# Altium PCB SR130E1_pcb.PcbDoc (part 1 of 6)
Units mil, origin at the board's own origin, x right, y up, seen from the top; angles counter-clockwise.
Board outline 5700 x 4800 mil, 6 copper layers (Top Layer, Signal Layer 1, Signal Layer 2, Signal Layer 3, Signal Layer 4, Bottom Layer), stack 61.4 mil thick; 452 components, 288 nets, 1391 pads, 911 vias.
Unrouted connection lines stored in the file: 523.
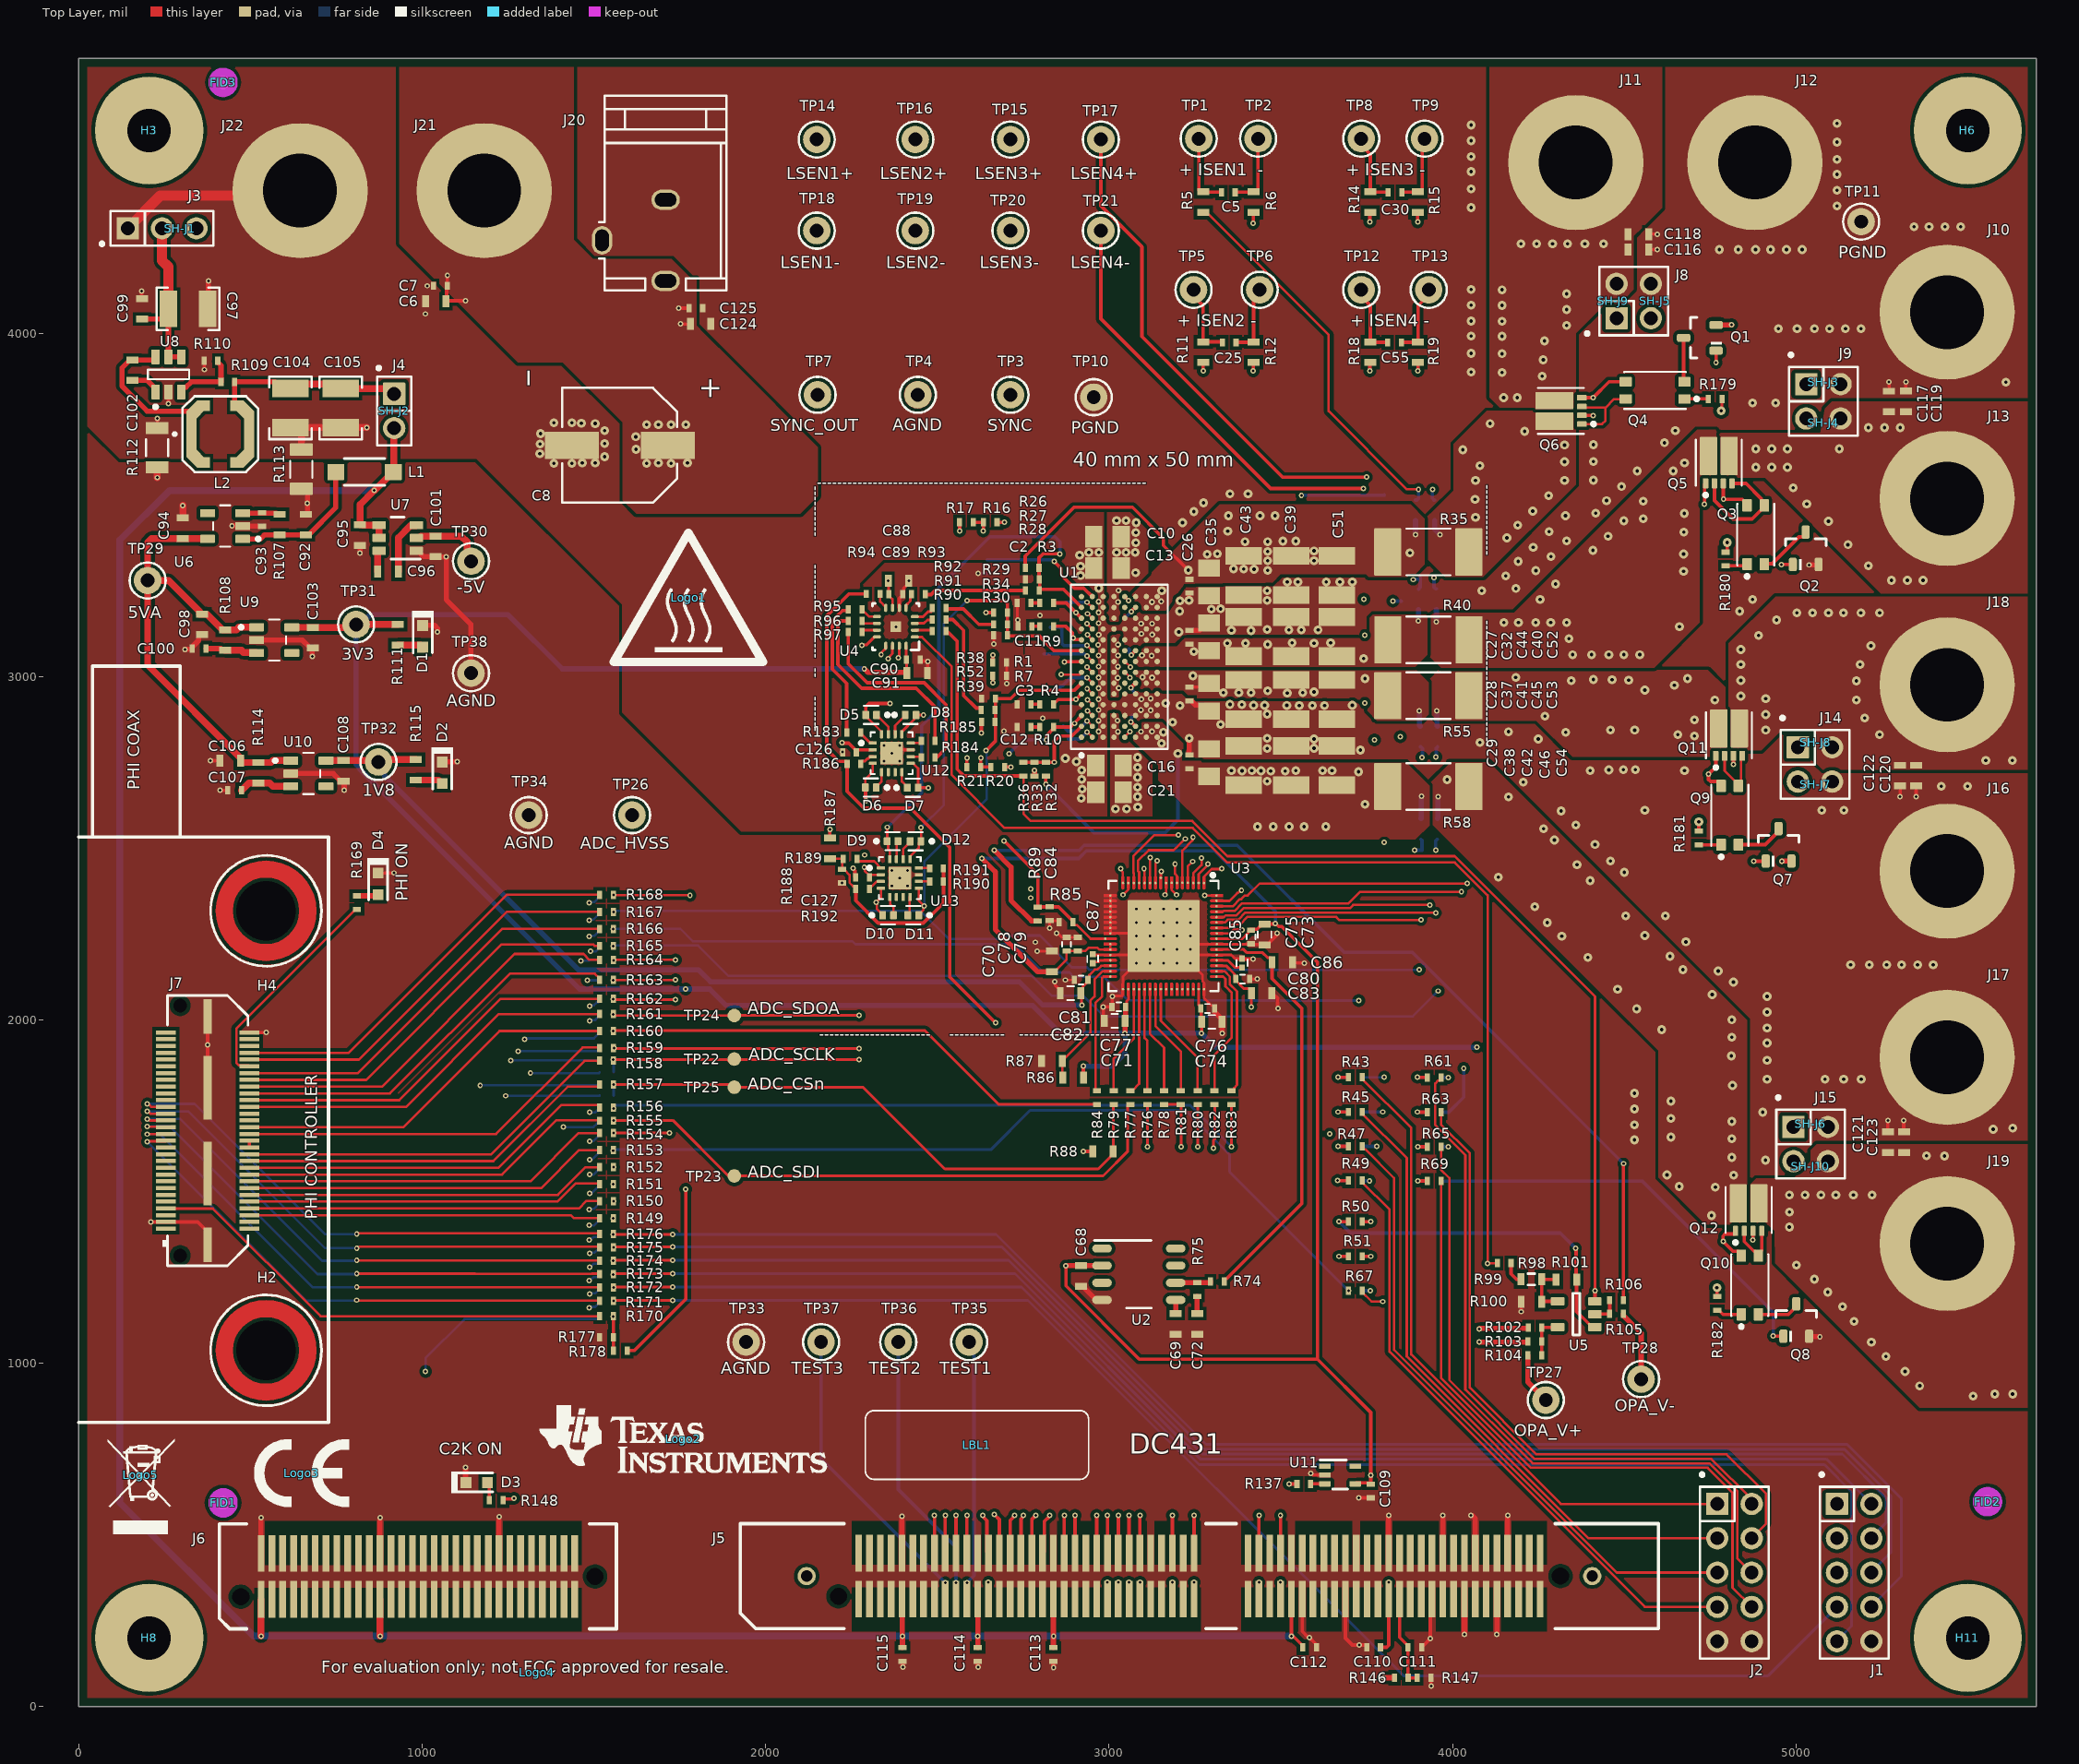
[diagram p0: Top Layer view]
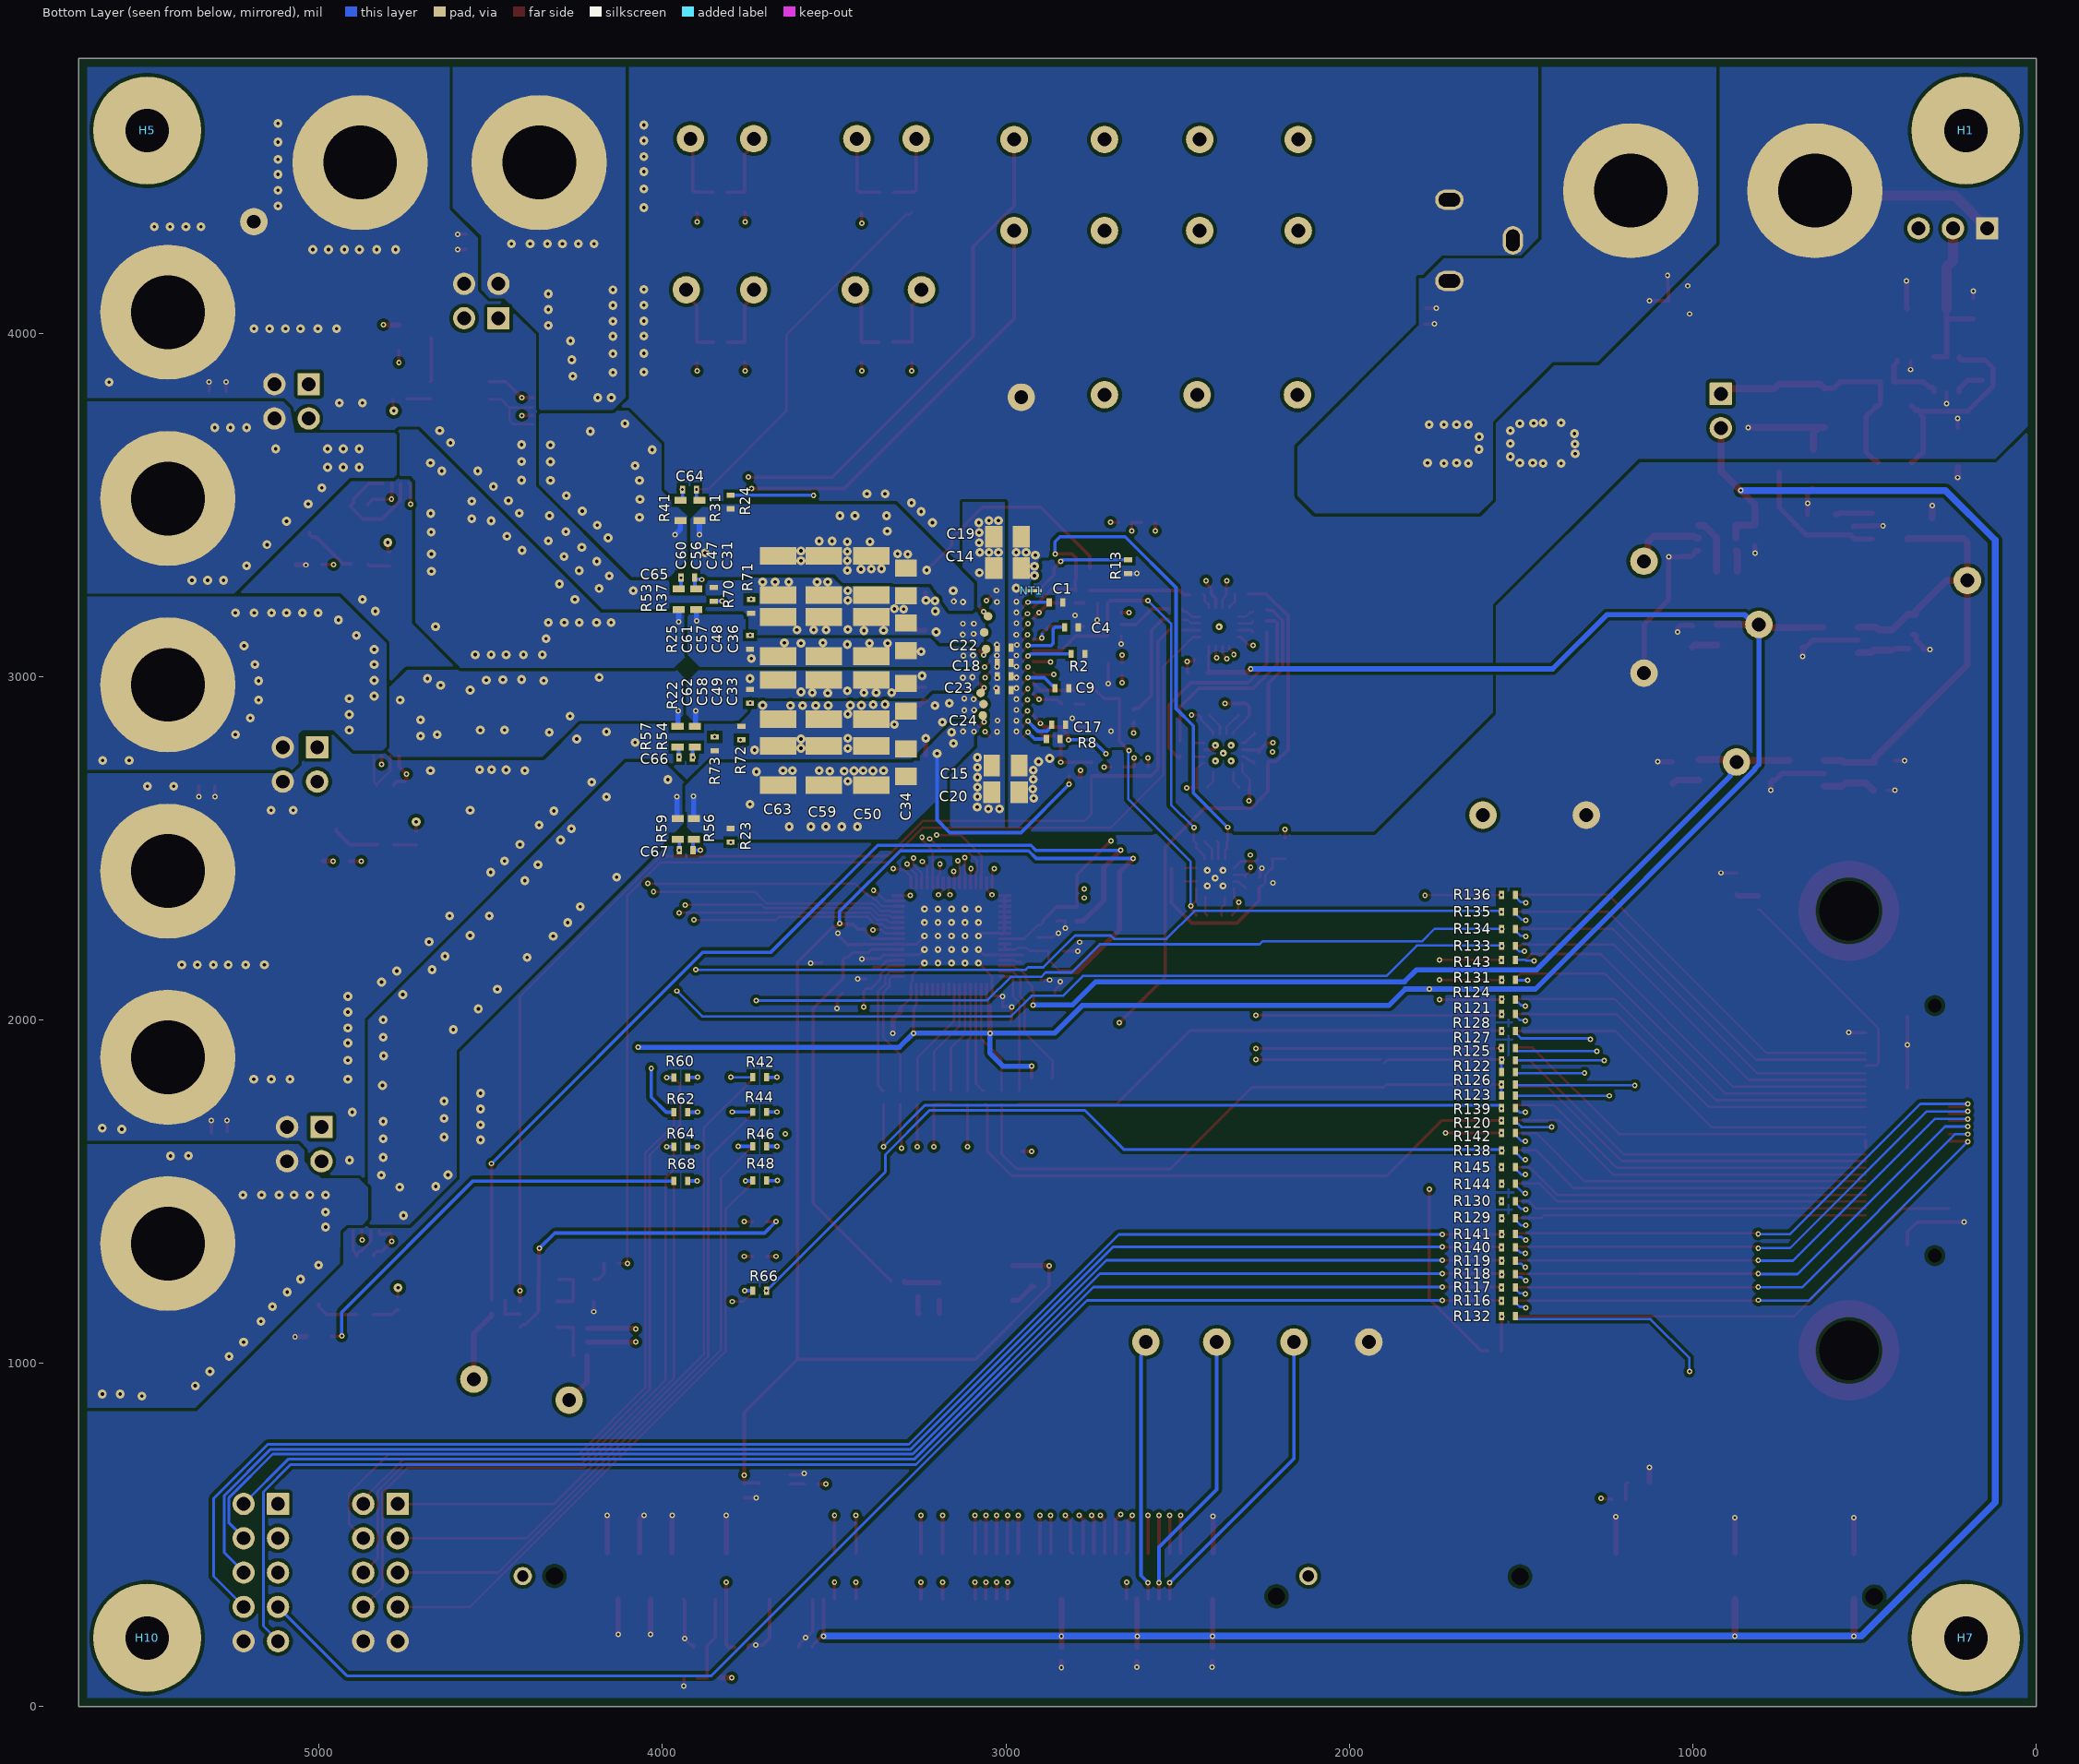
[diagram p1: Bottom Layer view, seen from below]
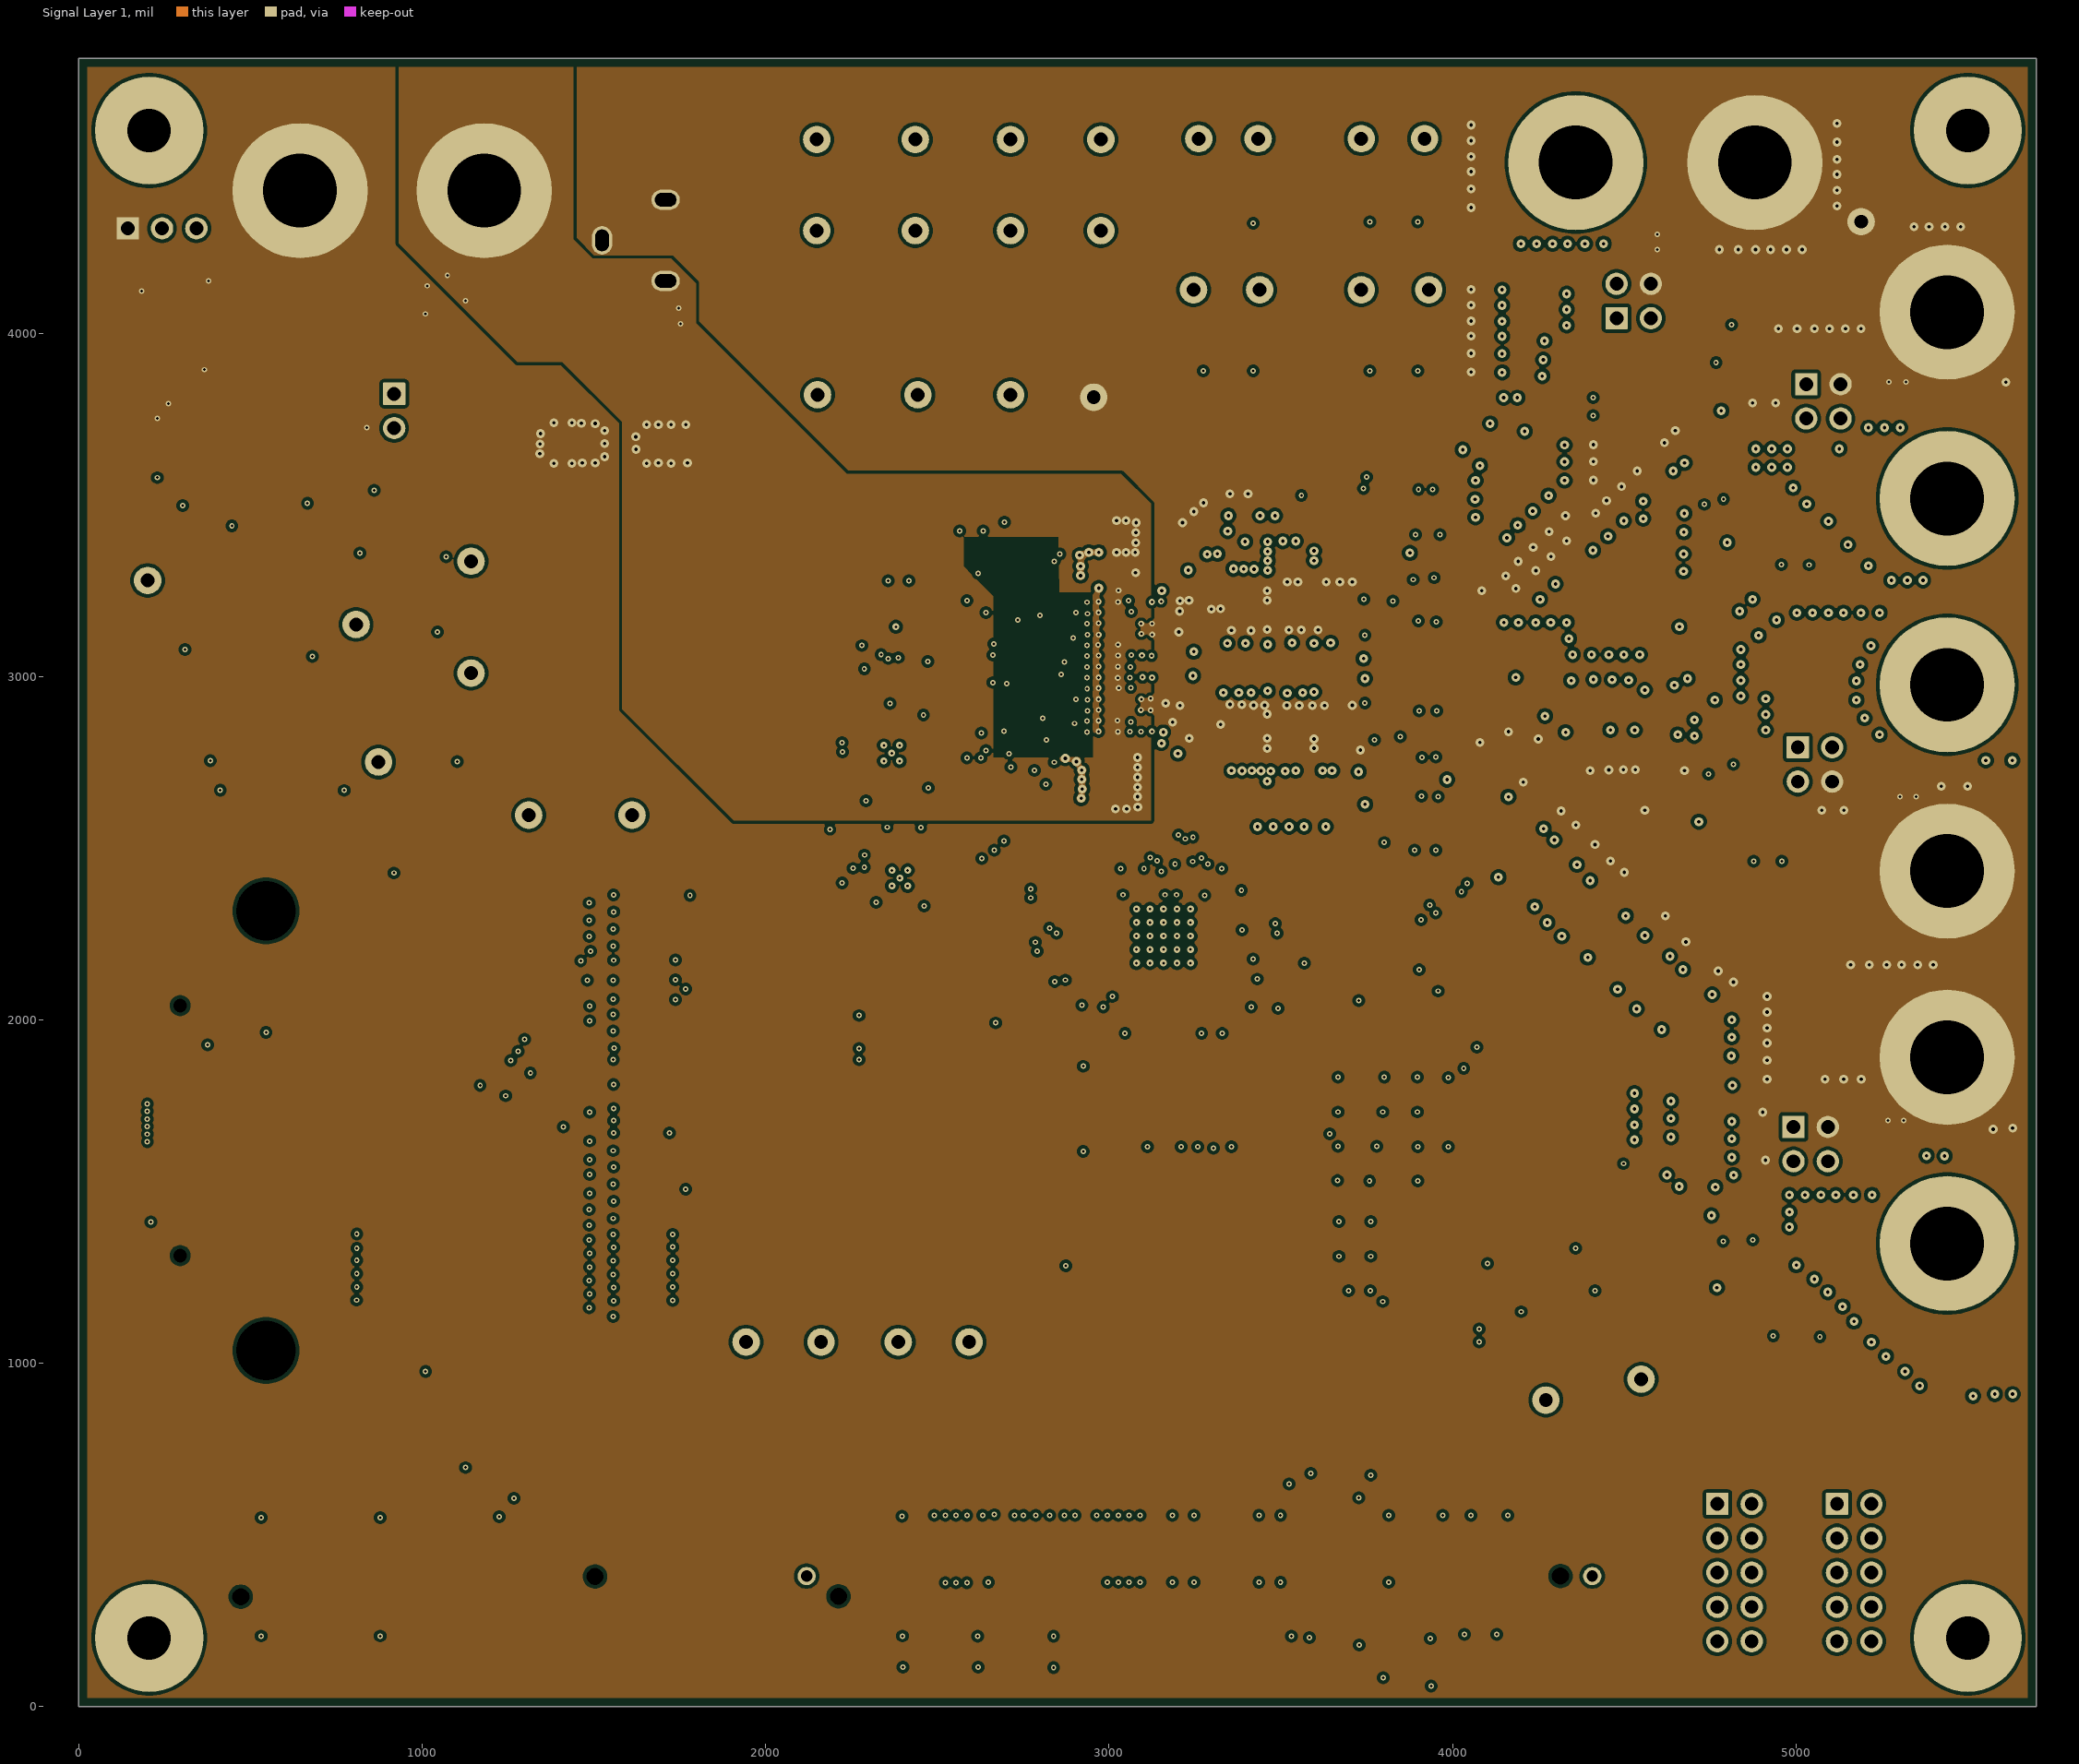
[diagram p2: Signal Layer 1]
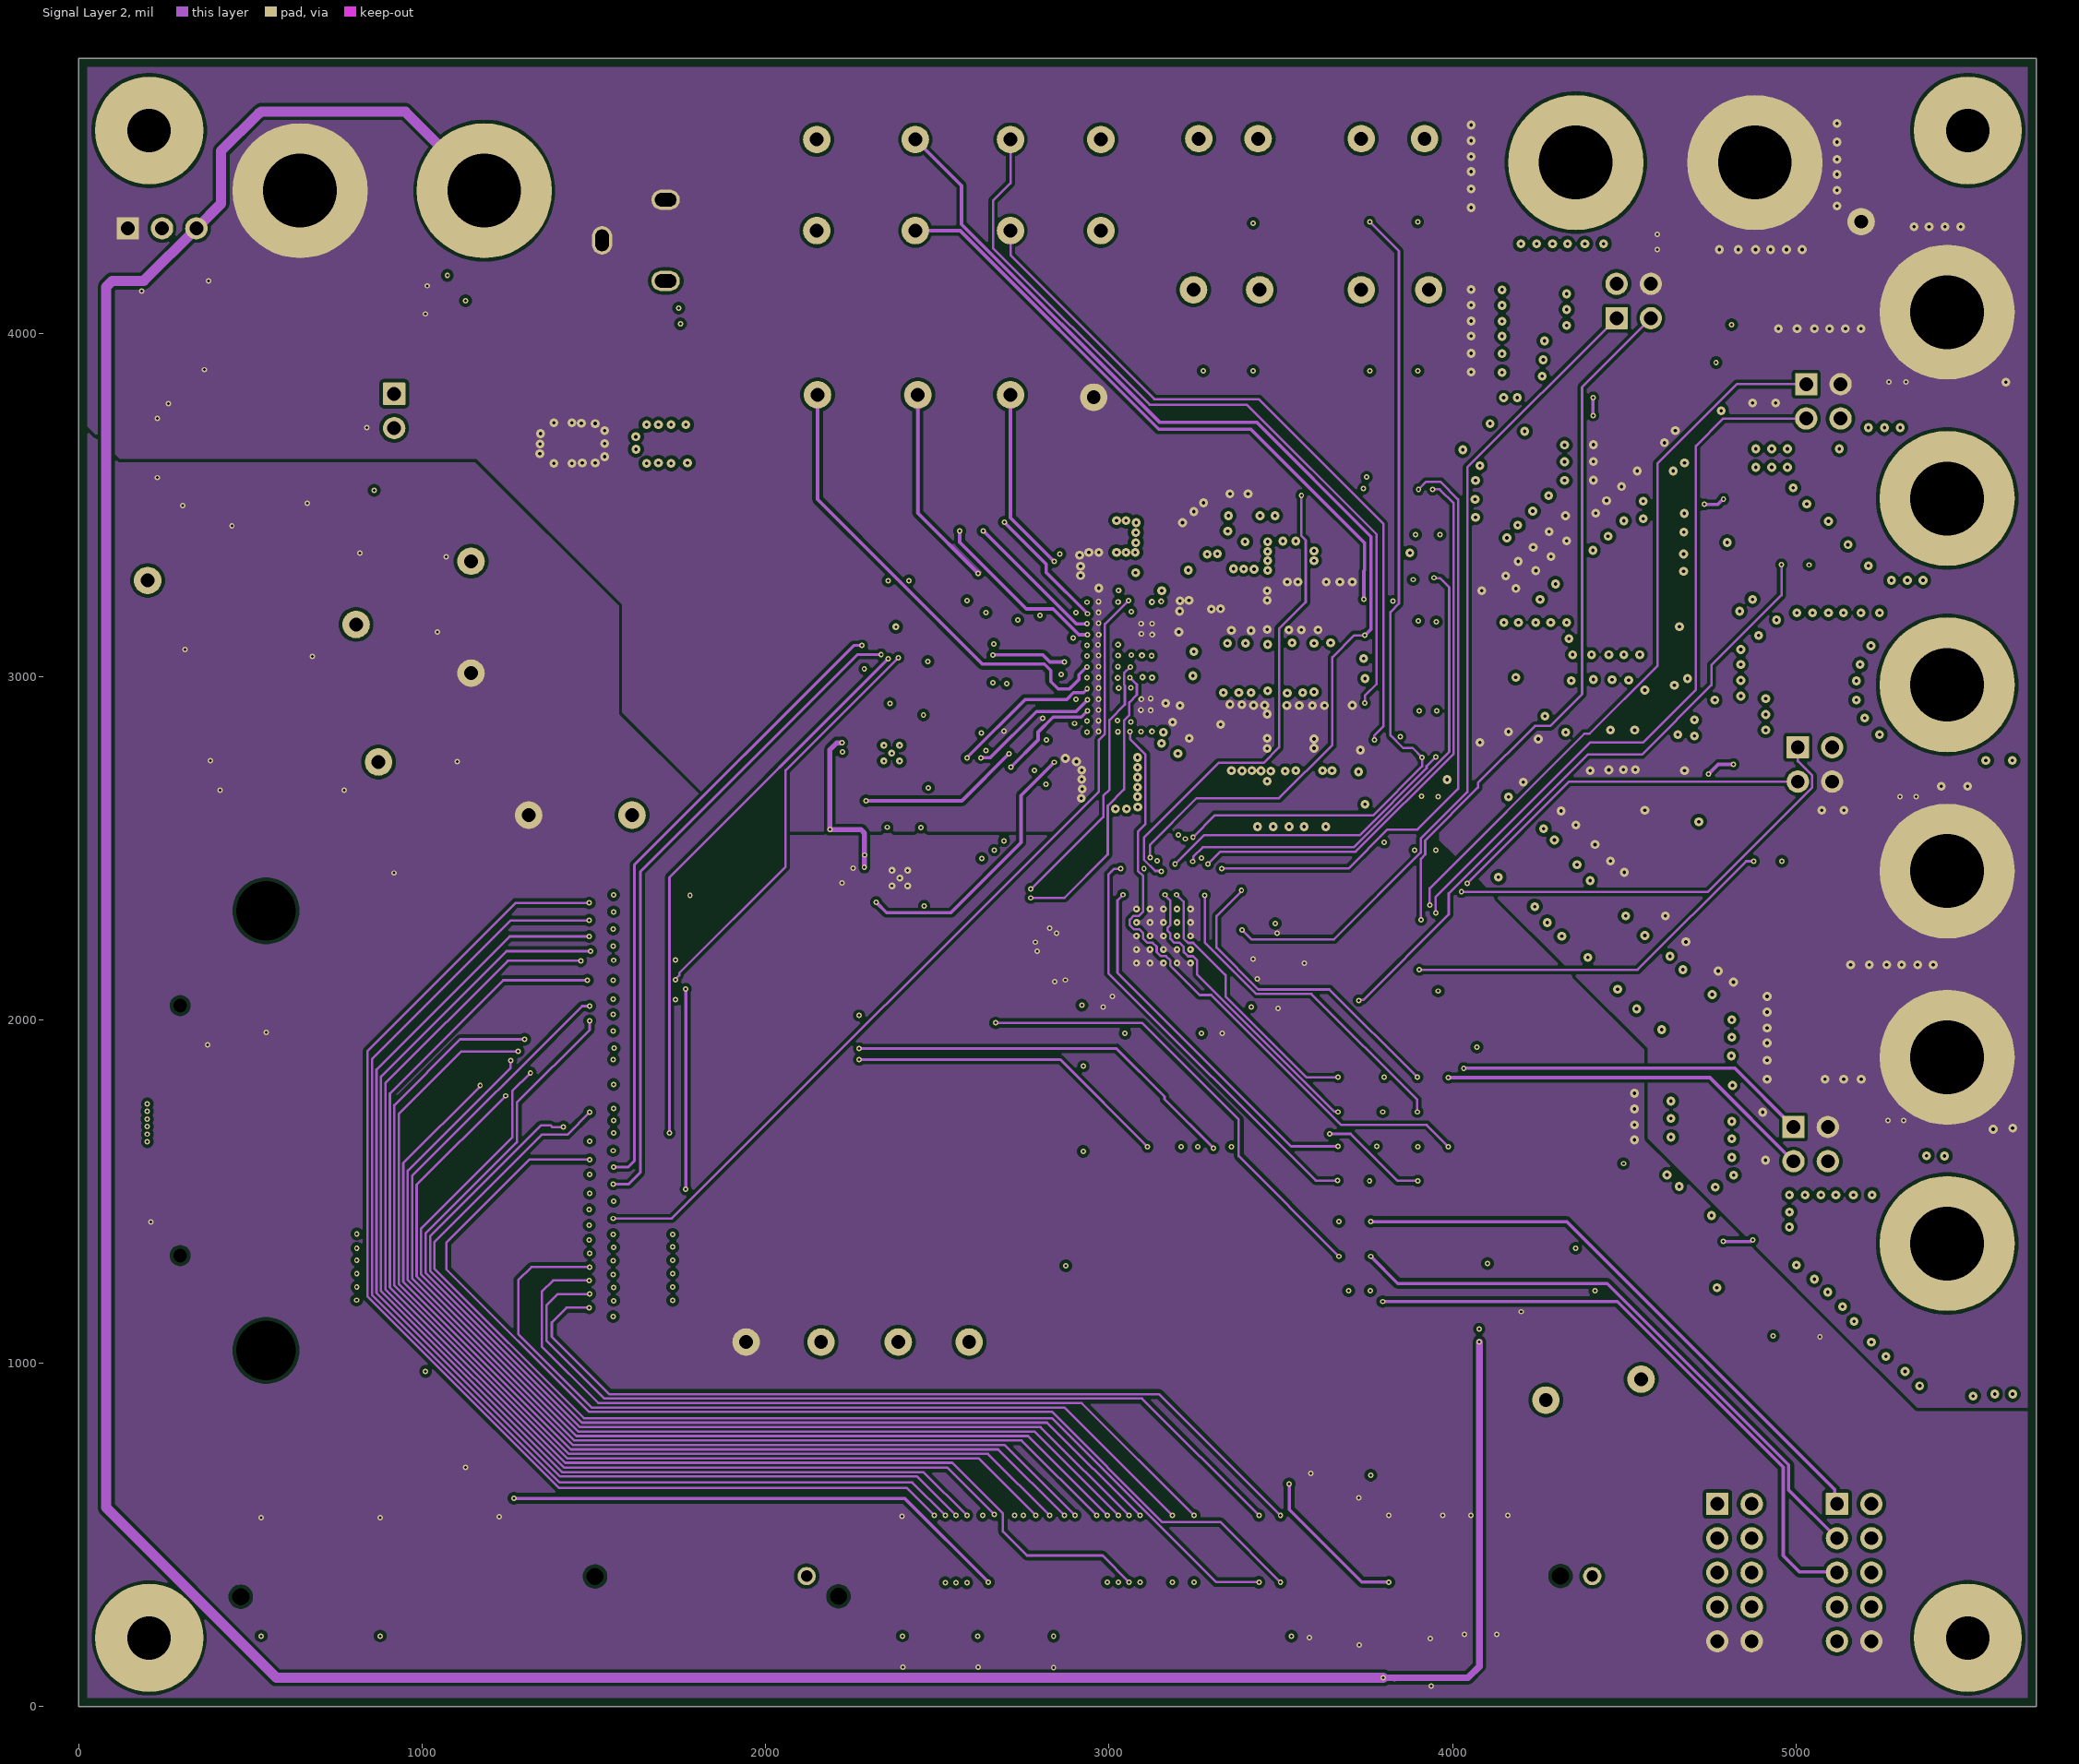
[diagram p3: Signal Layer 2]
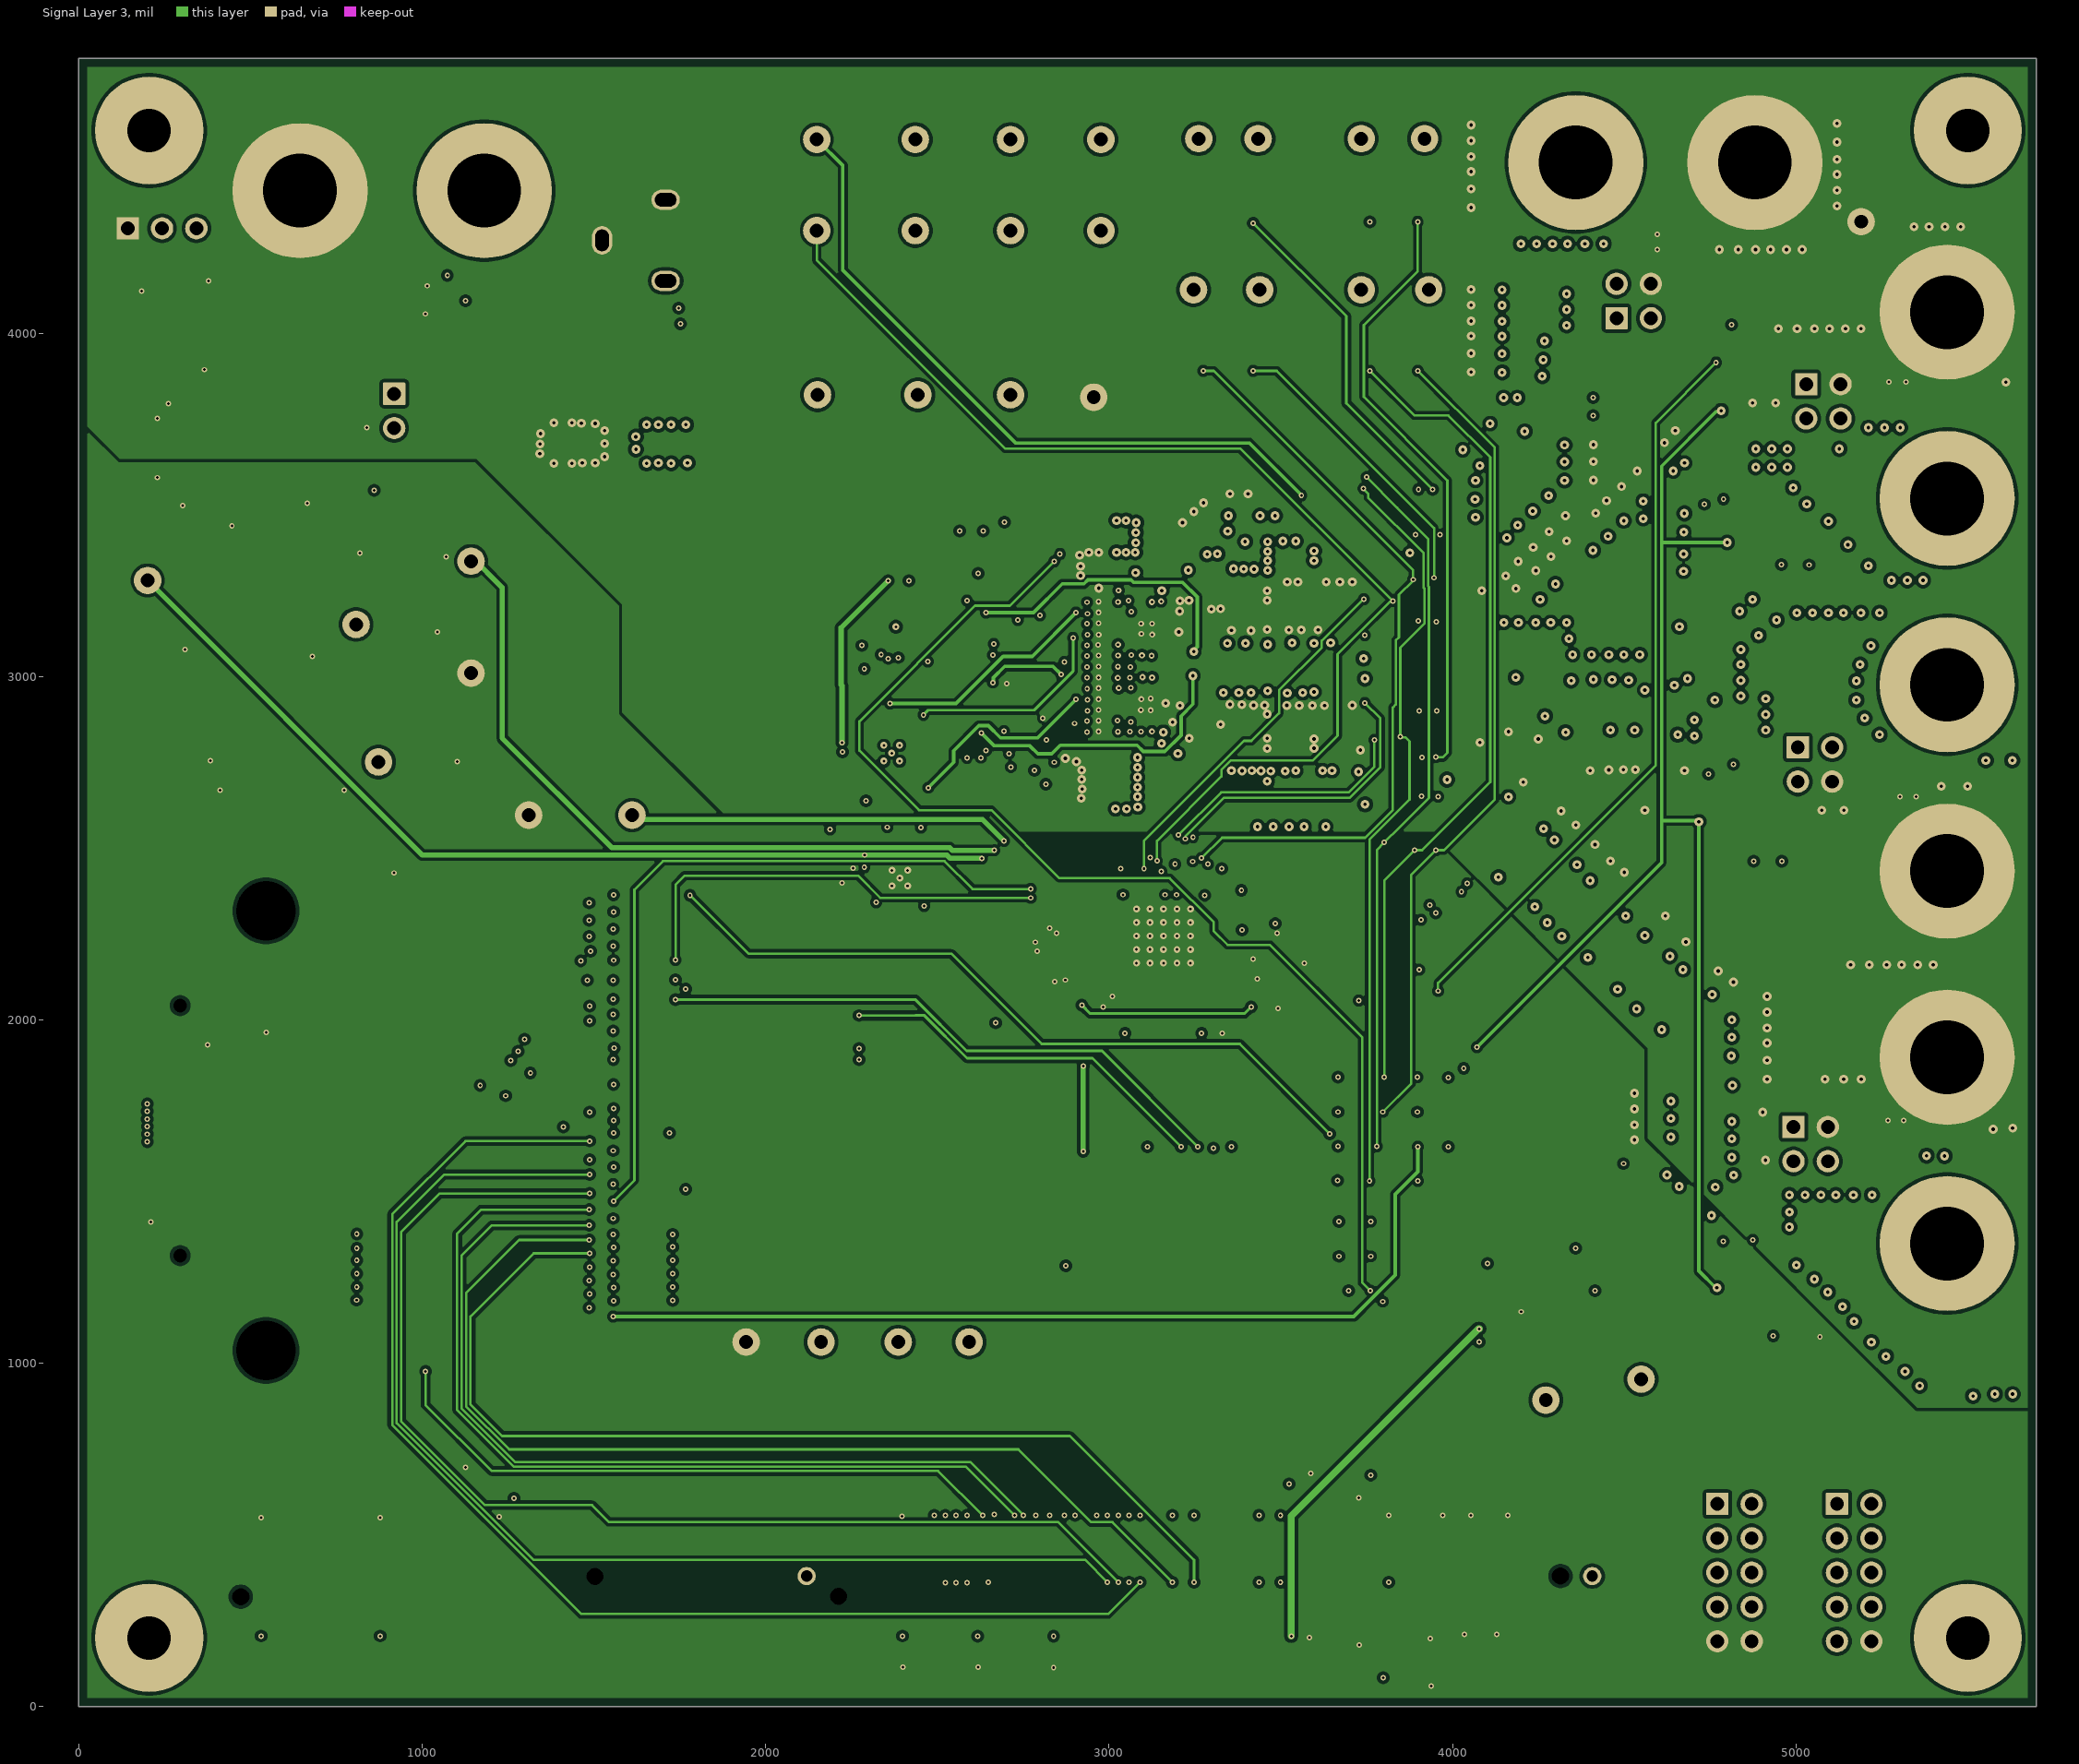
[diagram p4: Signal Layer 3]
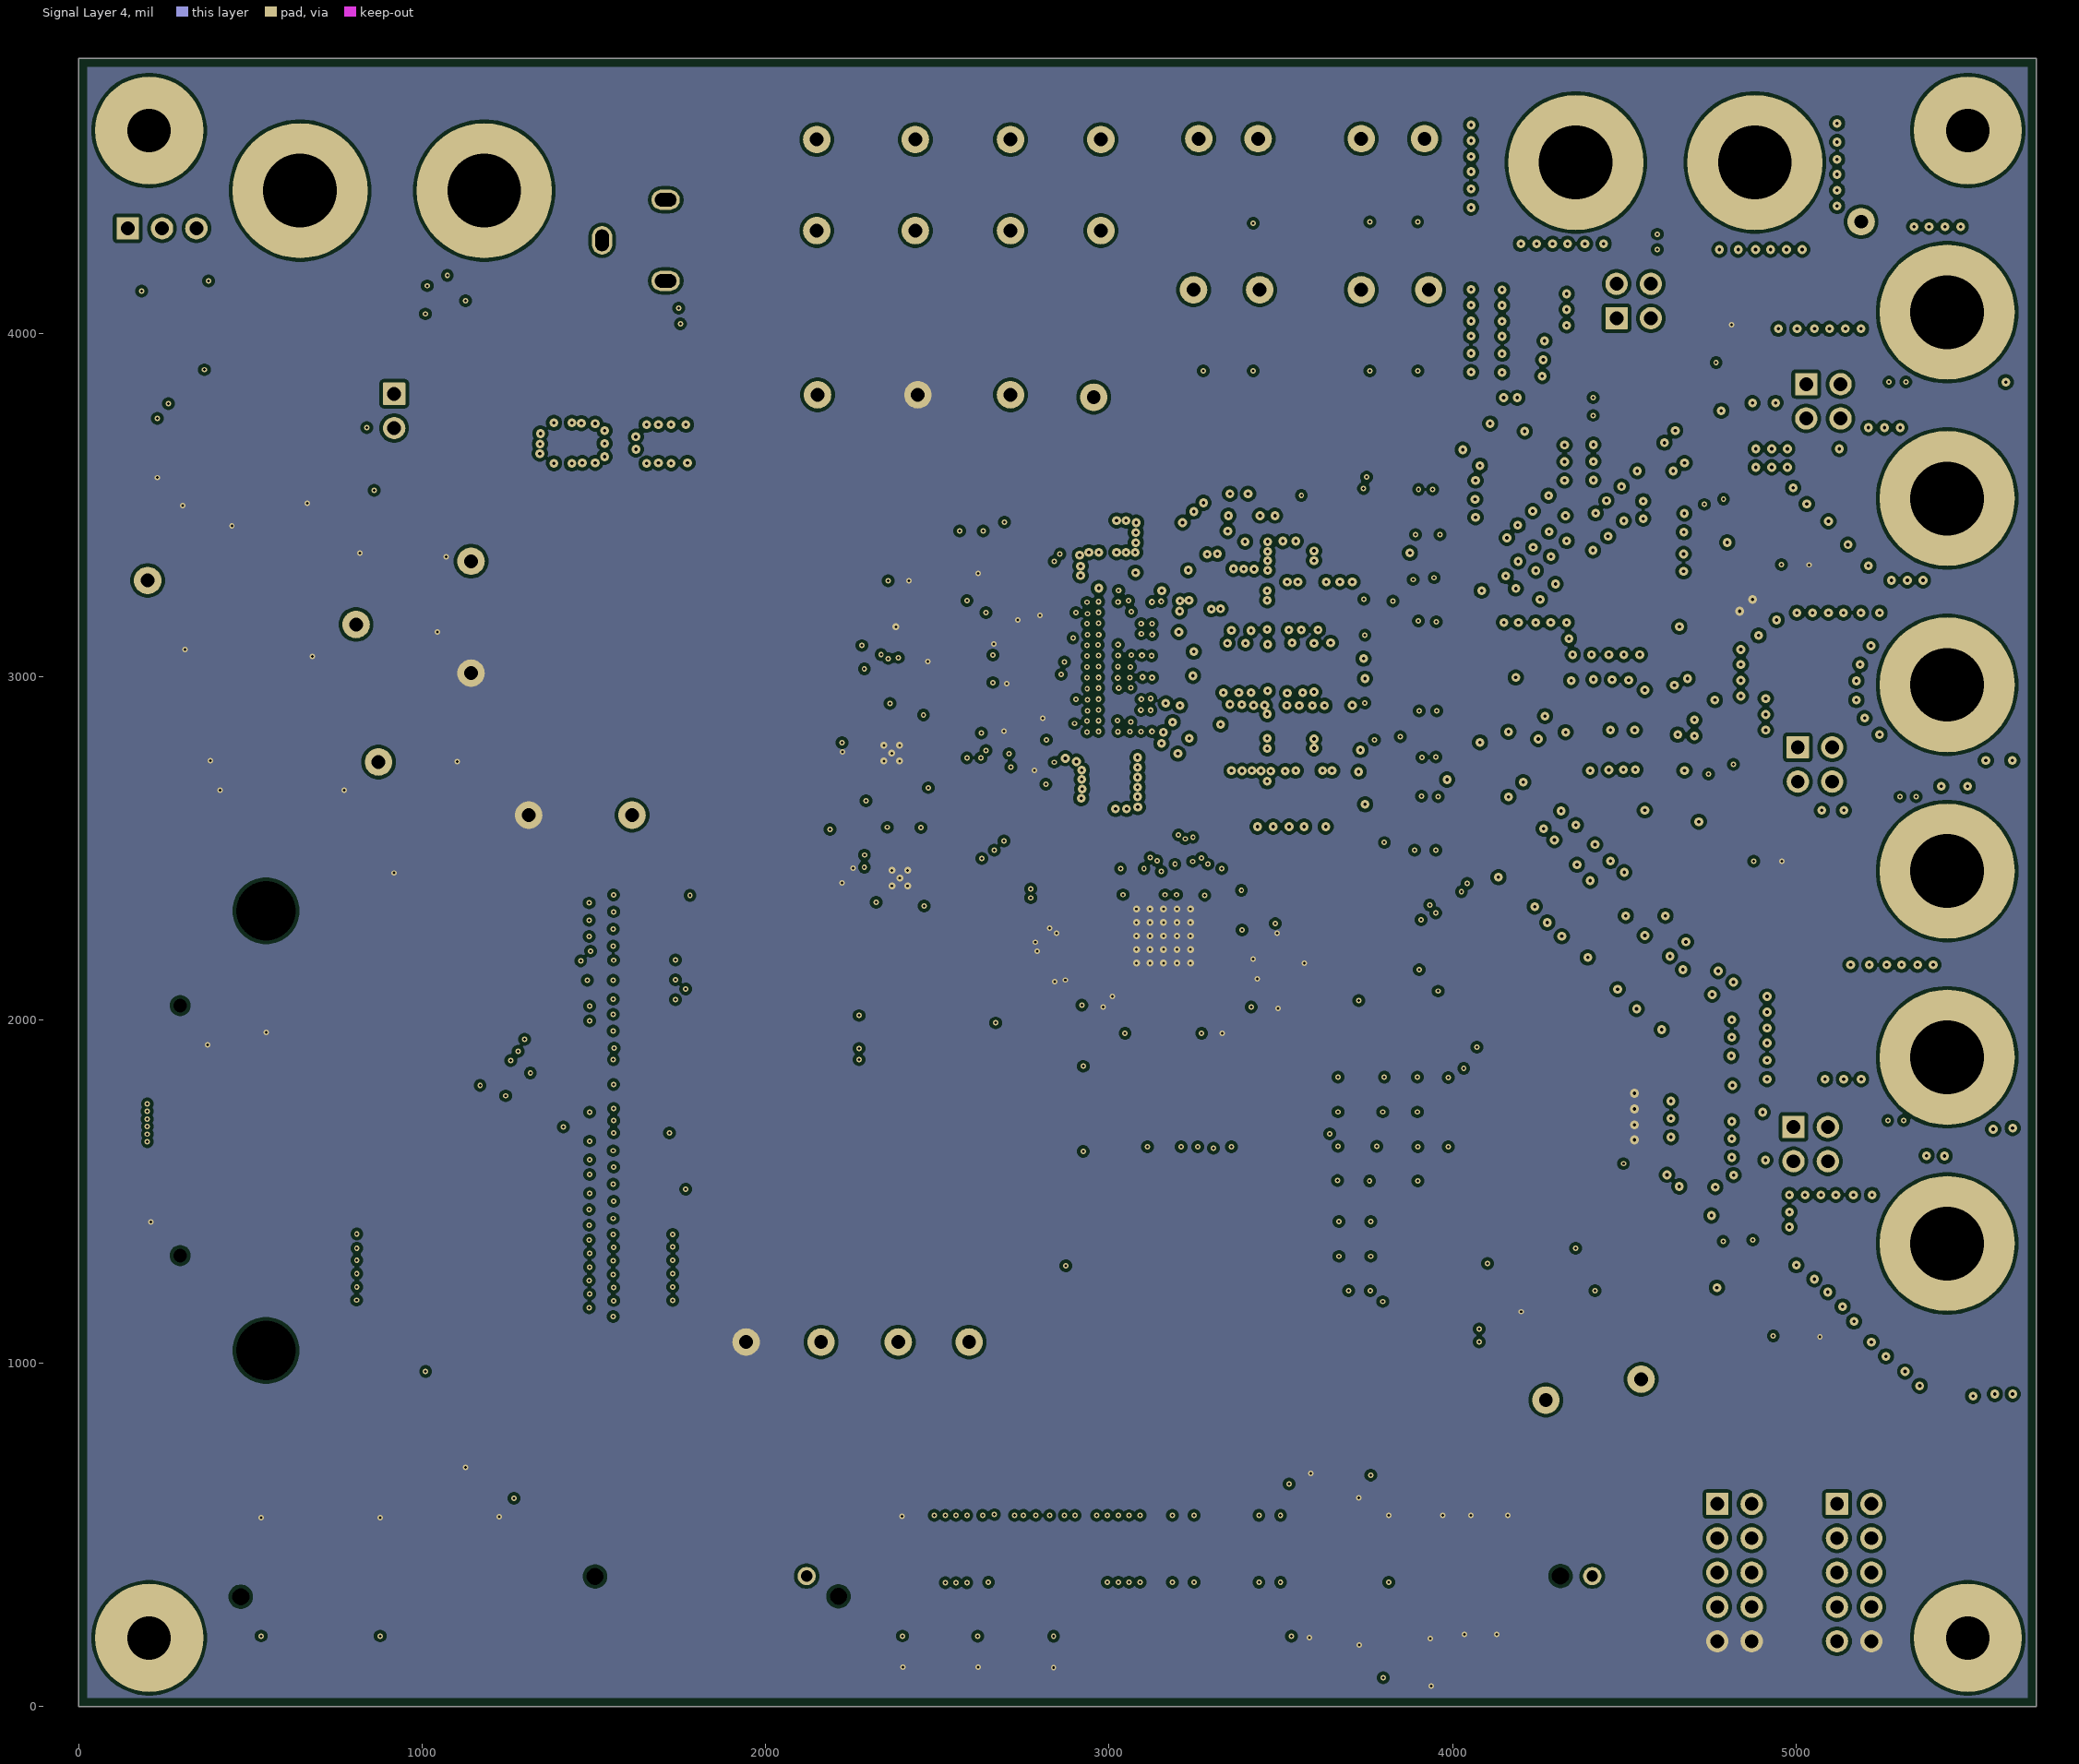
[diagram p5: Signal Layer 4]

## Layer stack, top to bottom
Top Solder: solder mask 0.5, Solder Resist, Dk 3.5
Top Layer: signal copper 1.4
Dielectric 1: prepreg 7, FR-4 High Tg, Dk 4.2
Signal Layer 1: signal copper 1.4
Dielectric 2: core 14, FR-4 High Tg, Dk 4.2
Signal Layer 2: signal copper 1.4
Dielectric 3: prepreg 11, FR-4 High Tg, Dk 4.2
Signal Layer 3: signal copper 1.4
Dielectric 4: core 14, FR-4 High Tg, Dk 4.2
Signal Layer 4: signal copper 1.4
Dielectric 5: prepreg 7, FR-4 High Tg, Dk 4.2
Bottom Layer: signal copper 1.4
Bottom Solder: solder mask 0.5, Solder Resist, Dk 3.5

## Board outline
0,0 0,4800 5700,4800 5700,0

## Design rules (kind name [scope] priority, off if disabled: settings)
AcuteAngle [All] p1: minimum=4.50000000000000E+0001 checktracksonly=FALSE
AssemblyTestPointUsage [All] p1: valid=2
BoardOutlineClearance BoardOutlineClearance_MountingHoles [OnCopper and InComponentClass('Mounting Holes')] p1: gap=39.37 ignorepadtopadclearanceinfootprint=FALSE
BoardOutlineClearance BoardOutlineClearance_Poly [OnCopper and IsPoly] p2: gap=25 ignorepadtopadclearanceinfootprint=FALSE
BoardOutlineClearance [OnCopper and Not InComponentClass('Logo') and not InComponentClass('FiducialMark') and not InRegion(1000,500,4000,800) and not InPoly] p3: gap=40 ignorepadtopadclearanceinfootprint=FALSE
Clearance Clearance_Keepouts [((IsTrack Or IsArc) And Not InPoly) And IsFree and IsKeepOut vs ((IsTrack Or IsArc) And Not InPoly) And IsFree and IsKeepOut] p1: gap=0 ignorepadtopadclearanceinfootprint=FALSE
Clearance Clearance_Poly [InPolygon] p2: gap=10 ignorepadtopadclearanceinfootprint=TRUE
Clearance Clearance_FiducialMark [IsKeepOut and InComponentClass('FiducialMark') vs IsPad and InComponentClass('FiducialMark')] p3: gap=0 ignorepadtopadclearanceinfootprint=FALSE
Clearance [All] p4: gap=6 ignorepadtopadclearanceinfootprint=TRUE
ComponentClearance ComponentClearance_MountingHoles_FiducialMarks [InComponentClass('Mounting Holes') vs InComponentClass('FiducialMark')] p1: gap=50 collisioncheckmode=3 verticalgap=10 showdistances=FALSE
ComponentClearance ComponentClearance_Shunt [InComponentClass('Header') vs InComponentClass('Shunt')] p2: gap=0 collisioncheckmode=3 verticalgap=0 showdistances=FALSE
ComponentClearance ComponentClearance_Logo [InComponentClass('Logo')] p3: gap=30 collisioncheckmode=3 verticalgap=10 showdistances=FALSE
ComponentClearance ComponentClearance_ScrewToNut [(HasFootprint('NY PMS 440 0025 PH')) vs (HasFootprint('Keystone_1902C'))] p4: gap=5 collisioncheckmode=3 verticalgap=10 showdistances=FALSE
ComponentClearance ComponentClearance_MountingHoles [InComponentClass('Mounting Holes')] p5: gap=100 collisioncheckmode=3 verticalgap=100000 showdistances=FALSE
ComponentClearance ComponentClearance_SmallPassives [HasFootprint('0201*') or HasFootprint('0402*') or HasFootprint('0508') or HasFootprint('0603*') or HasFootprint('0612') or HasFootprint('0805*') or HasFootprint('0815*') or HasFootprint('0830*') or HasFootprint('1206*') or HasFootprint('1210*') or HasFootprint('1808*') or HasFootprint('1812*') or HasFootprint('1825*') or HasFootprint('2010*') or HasFootprint('2220*') or HasFootprint('2225*') or HasFootprint('2512*') or HasFootprint('2728*') or HasFootprint('3518*') vs HasFootprint('0201*') or HasFootprint('0402*') or HasFootprint('0508') or HasFootprint('0603*') or HasFootprint('0612') or HasFootprint('0805*') or HasFootprint('0815*') or HasFootprint('0830*') or HasFootprint('1206*') or HasFootprint('1210*') or HasFootprint('1808*') or HasFootprint('1812*') or HasFootprint('1825*') or HasFootprint('2010*') or HasFootprint('2220*') or HasFootprint('2225*') or HasFootprint('2512*') or HasFootprint('2728*') or HasFootprint('3518*')] p6: gap=7 collisioncheckmode=3 verticalgap=10 showdistances=FALSE
ComponentClearance ComponentClearance_THtoSMT [IsThruComponent vs IsSMTComponent] p7: gap=30 collisioncheckmode=3 verticalgap=30 showdistances=FALSE
ComponentClearance ComponentClearance_THtoTH [IsThruComponent vs IsThruComponent] p8: gap=20 collisioncheckmode=3 verticalgap=30 showdistances=FALSE
ComponentClearance [All] p9: gap=20 collisioncheckmode=3 verticalgap=10 showdistances=FALSE
DiffPairsRouting [All] p1: maxlimit=100 minlimit=10 mostfreqgap=10 toplayer_minwidth=15 toplayer_maxwidth=15 toplayer_prefwidth=15 midlayer1_minwidth=15 midlayer1_maxwidth=15 midlayer1_prefwidth=15 midlayer2_minwidth=15 midlayer2_maxwidth=15 midlayer2_prefwidth=15 midlayer3_minwidth=15 midlayer3_maxwidth=15 midlayer3_prefwidth=15 midlayer4_minwidth=15 midlayer4_maxwidth=15 midlayer4_prefwidth=15 bottomlayer_minwidth=15 bottomlayer_maxwidth=15 bottomlayer_prefwidth=15 maxuncoupledlength=1000
FabricationTestPointUsage TestPointUsage [All] p1: valid=2 allowmultiple=FALSE
FabricationTestpoint Testpoint [All] p1: side=3 testpointundercomponent=TRUE minsize=40 maxsize=100 preferedsize=60 minholesize=0 maxholesize=40 preferedholesize=32 testpointgrid=1 allowsidetop=TRUE allowsidebottom=TRUE usegrid=TRUE gridtolerance=0.01
FanoutControl Fanout_LCC [IsLCC] p1: bgadir=Out bgaviamode=Centered fanoutstyle=Auto fanoutdirection=Alternating viagrid=1 // Fanout_LCC (Default Rule)
FanoutControl Fanout_BGA [IsBGA] p2: bgadir=Out bgaviamode=Centered fanoutstyle=Auto fanoutdirection=Alternating viagrid=1 // Fanout_BGA (Default Rule)
FanoutControl Fanout_Default [All] p4: bgadir=Out bgaviamode=Centered fanoutstyle=Auto fanoutdirection=Alternating viagrid=1 // Fanout_Default (Default Rule)
FanoutControl Fanout_Small [(CompPinCount < 5)] p5: bgadir=Out bgaviamode=Centered fanoutstyle=Auto fanoutdirection=OutThenIn viagrid=1 // Fanout_Small (Default Rule)
HoleSize [All] p1: absolutevalues=TRUE maxlimit=251 minlimit=7.87 maxpercent=80.000 minpercent=20.000
MinimumAnnularRing MinimumAnnularRing_ThermalPadVias [IsVia and InAnyComponent] p1: minimumring=5.8
MinimumAnnularRing [All] p2: minimumring=3.94
MinimumSolderMaskSliver MinimumSolderMaskSliver_Logo [InComponentClass('Logo') vs InComponentClass('Logo')] p1: minsoldermaskwidth=0.7
MinimumSolderMaskSliver [All] p2: minsoldermaskwidth=3.94
PlaneConnect [All] p1: planeconnectstyle=Relief reliefexpansion=10 reliefentries=4 reliefconductorwidth=10 reliefairgap=10
PolygonConnect PolygonConnect_66 [All vs IsNamedPolygon('LAYER_4_(BOT)_AGND_P033') Or IsNamedPolygon('LAYER_4_(BOT)_PGND_P045') Or IsNamedPolygon('LAYER_4_(BOT)_VIN_P040')] p1: connectstyle=Direct reliefconductorwidth=10 reliefentries=4 polygonreliefangle="90 Angle" airgapwidth=10
PolygonConnect PolygonConnect_65 [All vs IsNamedPolygon('LAYER_3_PGND_P052') Or IsNamedPolygon('LAYER_3_VOUT1_P044') Or IsNamedPolygon('LAYER_3_VOUT2_P047') Or IsNamedPolygon('LAYER_3_VOUT3_P049') Or IsNamedPolygon('LAYER_3_VOUT4_P051')] p2: connectstyle=Direct reliefconductorwidth=10 reliefentries=4 polygonreliefangle="90 Angle" airgapwidth=10
PolygonConnect PolygonConnect_64 [All vs IsNamedPolygon('LAYER_3_VOUT1_P047') Or IsNamedPolygon('LAYER_3_VOUT2_P049') Or IsNamedPolygon('LAYER_3_VOUT3_P051') Or IsNamedPolygon('LAYER_3_VOUT4_P052') Or IsNamedPolygon('LAYER_3_PGND_P053')] p3: connectstyle=Direct reliefconductorwidth=10 reliefentries=4 polygonreliefangle="90 Angle" airgapwidth=10
PolygonConnect PolygonConnect_63 [All vs IsNamedPolygon('LAYER_1_(TOP)_VIN_P039')] p4: connectstyle=Direct reliefconductorwidth=10 reliefentries=4 polygonreliefangle="90 Angle" airgapwidth=10
PolygonConnect PolygonConnect_62 [All vs IsNamedPolygon('LAYER_1_(TOP)_VOUT1_P031') Or IsNamedPolygon('LAYER_1_(TOP)_VOUT2_P032') Or IsNamedPolygon('LAYER_1_(TOP)_VOUT3_P036') Or IsNamedPolygon('LAYER_1_(TOP)_VOUT4_P038')] p5: connectstyle=Direct reliefconductorwidth=10 reliefentries=4 polygonreliefangle="90 Angle" airgapwidth=10
PolygonConnect PolygonConnect_61 [All vs IsNamedPolygon('LAYER_1_(TOP)_VIN_P024') Or IsNamedPolygon('LAYER_1_(TOP)_VIN_P025') Or IsNamedPolygon('LAYER_1_(TOP)_VIN_P027')] p6: connectstyle=Direct reliefconductorwidth=10 reliefentries=4 polygonreliefangle="90 Angle" airgapwidth=10
PolygonConnect PolygonConnect_60 [All vs IsNamedPolygon('LAYER_1_(TOP)_AGND_P030')] p7: connectstyle=Direct reliefconductorwidth=10 reliefentries=4 polygonreliefangle="90 Angle" airgapwidth=10
PolygonConnect PolygonConnect_59 [All vs IsNamedPolygon('LAYER_2_VIN_P034') Or IsNamedPolygon('LAYER_3_VOUT1_P035') Or IsNamedPolygon('LAYER_3_VOUT2_P041') Or IsNamedPolygon('LAYER_3_VOUT3_P042') Or IsNamedPolygon('LAYER_3_VOUT4_P043')] p8: connectstyle=Direct reliefconductorwidth=10 reliefentries=4 polygonreliefangle="90 Angle" airgapwidth=10
PolygonConnect PolygonConnect_58 [All vs IsNamedPolygon('LAYER_1_(TOP)_PGND_P046') Or IsNamedPolygon('LAYER_2_PGND_P037') Or IsNamedPolygon('LAYER_3_PGND_P047')] p9: connectstyle=Direct reliefconductorwidth=10 reliefentries=4 polygonreliefangle="90 Angle" airgapwidth=10
PolygonConnect PolygonConnect_57 [All vs IsNamedPolygon('LAYER_4_PGND_P048') Or IsNamedPolygon('LAYER_5_PGND_P044') Or IsNamedPolygon('LAYER_6_(BOT)_AGND_P033') Or IsNamedPolygon('LAYER_6_(BOT)_PGND_P045') Or IsNamedPolygon('LAYER_6_(BOT)_VIN_P040')] p10: connectstyle=Direct reliefconductorwidth=10 reliefentries=4 polygonreliefangle="90 Angle" airgapwidth=10
PolygonConnect PolygonConnect_56 [All vs IsNamedPolygon('LAYER_6_(BOT)_AGND_P006') Or IsNamedPolygon('LAYER_6_(BOT)_PGND_P020') Or IsNamedPolygon('LAYER_6_(BOT)_VIN_P015')] p11: connectstyle=Direct reliefconductorwidth=10 reliefentries=4 polygonreliefangle="90 Angle" airgapwidth=10
PolygonConnect PolygonConnect_55 [All vs IsNamedPolygon('LAYER_5_PGND_P019') Or IsNamedPolygon('LAYER_3_VOUT1_P008') Or IsNamedPolygon('LAYER_3_VOUT2_P016') Or IsNamedPolygon('LAYER_3_VOUT3_P017') Or IsNamedPolygon('LAYER_3_VOUT4_P018')] p12: connectstyle=Direct reliefconductorwidth=10 reliefentries=4 polygonreliefangle="90 Angle" airgapwidth=10
PolygonConnect PolygonConnect_54 [All vs IsNamedPolygon('LAYER_5_PGND_P019')] p13: connectstyle=Direct reliefconductorwidth=10 reliefentries=4 polygonreliefangle="90 Angle" airgapwidth=10
PolygonConnect PolygonConnect_53 [All vs IsNamedPolygon('LAYER_4_PGND_P023')] p14: connectstyle=Direct reliefconductorwidth=10 reliefentries=4 polygonreliefangle="90 Angle" airgapwidth=10
PolygonConnect PolygonConnect_52 [All vs IsNamedPolygon('LAYER_3_PGND_P022')] p15: connectstyle=Direct reliefconductorwidth=10 reliefentries=4 polygonreliefangle="90 Angle" airgapwidth=10
PolygonConnect PolygonConnect_51 [All vs IsNamedPolygon('LAYER_1_(TOP)_AGND_P002')] p16: connectstyle=Direct reliefconductorwidth=10 reliefentries=4 polygonreliefangle="90 Angle" airgapwidth=10
PolygonConnect PolygonConnect_50 [All vs IsNamedPolygon('LAYER_1_(TOP)_VIN_P000') Or IsNamedPolygon('LAYER_1_(TOP)_VIN_P014')] p17: connectstyle=Direct reliefconductorwidth=10 reliefentries=4 polygonreliefangle="90 Angle" airgapwidth=10
PolygonConnect PolygonConnect_49 [All vs IsNamedPolygon('LAYER_1_(TOP)_VOUT2_P005') Or IsNamedPolygon('LAYER_1_(TOP)_VOUT3_P011') Or IsNamedPolygon('LAYER_1_(TOP)_VOUT4_P013')] p18: connectstyle=Direct reliefconductorwidth=10 reliefentries=4 polygonreliefangle="90 Angle" airgapwidth=10
PolygonConnect PolygonConnect_48 [All vs IsNamedPolygon('LAYER_1_(TOP)_VOUT2_P005')] p19: connectstyle=Direct reliefconductorwidth=10 reliefentries=4 polygonreliefangle="90 Angle" airgapwidth=10
PolygonConnect PolygonConnect_47 [All vs IsNamedPolygon('LAYER_1_(TOP)_VOUT1_P003')] p20: connectstyle=Direct reliefconductorwidth=10 reliefentries=4 polygonreliefangle="90 Angle" airgapwidth=10
PolygonConnect PolygonConnect_46 [All vs IsNamedPolygon('LAYER_1_(TOP)_PGND_P021')] p21: connectstyle=Direct reliefconductorwidth=10 reliefentries=4 polygonreliefangle="90 Angle" airgapwidth=10
PolygonConnect PolygonConnect_45 [All vs IsNamedPolygon('LAYER_1_(TOP)_VIN_P001')] p22: connectstyle=Direct reliefconductorwidth=10 reliefentries=4 polygonreliefangle="90 Angle" airgapwidth=10
PolygonConnect PolygonConnect_44 [All vs IsNamedPolygon('LAYER_1_(TOP)_VOUT4_P011')] p23: connectstyle=Direct reliefconductorwidth=10 reliefentries=4 polygonreliefangle="90 Angle" airgapwidth=10
PolygonConnect PolygonConnect_43 [All vs IsNamedPolygon('LAYER_1_(TOP)_VOUT3_P005')] p24: connectstyle=Direct reliefconductorwidth=10 reliefentries=4 polygonreliefangle="90 Angle" airgapwidth=10
PolygonConnect PolygonConnect_42 [All vs IsNamedPolygon('LAYER_1_(TOP)_VOUT2_P003')] p25: connectstyle=Direct reliefconductorwidth=10 reliefentries=4 polygonreliefangle="90 Angle" airgapwidth=10
PolygonConnect PolygonConnect_41 [All vs IsNamedPolygon('LAYER_1_(TOP)_VOUT1_P002')] p26: connectstyle=Direct reliefconductorwidth=10 reliefentries=4 polygonreliefangle="90 Angle" airgapwidth=10
PolygonConnect PolygonConnect_40 [All vs IsNamedPolygon('LAYER_1_(TOP)_PGND_P014')] p27: connectstyle=Direct reliefconductorwidth=10 reliefentries=4 polygonreliefangle="90 Angle" airgapwidth=10
PolygonConnect PolygonConnect_39 [All vs IsNamedPolygon('LAYER_1_(TOP)_AGND_P000')] p28: connectstyle=Direct reliefconductorwidth=10 reliefentries=4 polygonreliefangle="90 Angle" airgapwidth=10
PolygonConnect PolygonConnect_38 [All vs IsNamedPolygon('LAYER_1_(TOP)_AGND_P011')] p29: connectstyle=Direct reliefconductorwidth=10 reliefentries=4 polygonreliefangle="90 Angle" airgapwidth=10
PolygonConnect PolygonConnect_37 [All vs IsNamedPolygon('LAYER_4_(BOT)_AGND_P006')] p30: connectstyle=Direct reliefconductorwidth=10 reliefentries=4 polygonreliefangle="90 Angle" airgapwidth=10
PolygonConnect PolygonConnect_36 [All vs IsNamedPolygon('LAYER_4_(BOT)_VIN_P015')] p31: connectstyle=Direct reliefconductorwidth=10 reliefentries=4 polygonreliefangle="90 Angle" airgapwidth=10
PolygonConnect PolygonConnect_35 [All vs IsNamedPolygon('LAYER_4_(BOT)_PGND_P020')] p32: connectstyle=Direct reliefconductorwidth=10 reliefentries=4 polygonreliefangle="90 Angle" airgapwidth=10
PolygonConnect PolygonConnect_34 [All vs IsNamedPolygon('LAYER_3_PGND_P019')] p33: connectstyle=Direct reliefconductorwidth=10 reliefentries=4 polygonreliefangle="90 Angle" airgapwidth=10
PolygonConnect PolygonConnect_33 [All vs IsNamedPolygon('LAYER_3_VOUT4_P018')] p34: connectstyle=Direct reliefconductorwidth=10 reliefentries=4 polygonreliefangle="90 Angle" airgapwidth=10
PolygonConnect PolygonConnect_32 [All vs IsNamedPolygon('LAYER_3_VOUT3_P017')] p35: connectstyle=Direct reliefconductorwidth=10 reliefentries=4 polygonreliefangle="90 Angle" airgapwidth=10
PolygonConnect PolygonConnect_31 [All vs IsNamedPolygon('LAYER_3_VOUT2_P016')] p36: connectstyle=Direct reliefconductorwidth=10 reliefentries=4 polygonreliefangle="90 Angle" airgapwidth=10
PolygonConnect PolygonConnect_30 [All vs IsNamedPolygon('LAYER_3_VOUT1_P008')] p37: connectstyle=Direct reliefconductorwidth=10 reliefentries=4 polygonreliefangle="90 Angle" airgapwidth=10
PolygonConnect PolygonConnect_29 [All vs IsNamedPolygon('LAYER_1_(TOP)_VIN_P013')] p38: connectstyle=Direct reliefconductorwidth=10 reliefentries=4 polygonreliefangle="90 Angle" airgapwidth=10
PolygonConnect PolygonConnect_28 [All vs IsNamedPolygon('LAYER_4_(BOT)_VIN_P006')] p39: connectstyle=Direct reliefconductorwidth=10 reliefentries=4 polygonreliefangle="90 Angle" airgapwidth=10
PolygonConnect PolygonConnect_27 [All vs IsNamedPolygon('LAYER_4_(BOT)_PGND_P015')] p40: connectstyle=Direct reliefconductorwidth=10 reliefentries=4 polygonreliefangle="90 Angle" airgapwidth=10
PolygonConnect PolygonConnect_26 [All vs IsNamedPolygon('LAYER_4_(BOT)_PGND_P006')] p41: connectstyle=Direct reliefconductorwidth=10 reliefentries=4 polygonreliefangle="90 Angle" airgapwidth=10
PolygonConnect PolygonConnect_25 [All vs IsNamedPolygon('LAYER_3_PGND_P008')] p42: connectstyle=Direct reliefconductorwidth=10 reliefentries=4 polygonreliefangle="90 Angle" airgapwidth=10
PolygonConnect PolygonConnect_24 [All vs IsNamedPolygon('LAYER_1_(TOP)_AGND_P011')] p43: connectstyle=Direct reliefconductorwidth=10 reliefentries=4 polygonreliefangle="90 Angle" airgapwidth=10
PolygonConnect PolygonConnect_23 [All vs IsNamedPolygon('LAYER_1_(TOP)_VOUT4_P005')] p44: connectstyle=Direct reliefconductorwidth=10 reliefentries=4 polygonreliefangle="90 Angle" airgapwidth=10
PolygonConnect PolygonConnect_22 [All vs IsNamedPolygon('LAYER_1_(TOP)_VOUT3_P003')] p45: connectstyle=Direct reliefconductorwidth=10 reliefentries=4 polygonreliefangle="90 Angle" airgapwidth=10
PolygonConnect PolygonConnect_21 [All vs IsNamedPolygon('LAYER_1_(TOP)_VOUT2_P002')] p46: connectstyle=Direct reliefconductorwidth=10 reliefentries=4 polygonreliefangle="90 Angle" airgapwidth=10
PolygonConnect PolygonConnect_20 [All vs IsNamedPolygon('LAYER_1_(TOP)_VOUT1_P001')] p47: connectstyle=Direct reliefconductorwidth=10 reliefentries=4 polygonreliefangle="90 Angle" airgapwidth=10
PolygonConnect PolygonConnect_19 [All vs IsNamedPolygon('LAYER_1_(TOP)_PGND_P014')] p48: connectstyle=Direct reliefconductorwidth=10 reliefentries=4 polygonreliefangle="90 Angle" airgapwidth=10
PolygonConnect PolygonConnect_18 [All vs IsNamedPolygon('LAYER_2_PGND_P012')] p49: connectstyle=Direct reliefconductorwidth=10 reliefentries=4 polygonreliefangle="90 Angle" airgapwidth=10
PolygonConnect PolygonConnect_17 [All vs IsNamedPolygon('LAYER_2_VOUT2_P010')] p50: connectstyle=Direct reliefconductorwidth=10 reliefentries=4 polygonreliefangle="90 Angle" airgapwidth=10
PolygonConnect PolygonConnect_16 [All vs IsNamedPolygon('LAYER_2_VOUT1_P009')] p51: connectstyle=Direct reliefconductorwidth=10 reliefentries=4 polygonreliefangle="90 Angle" airgapwidth=10
PolygonConnect PolygonConnect_15 [All vs IsNamedPolygon('LAYER_1_(TOP)_PGND_P011')] p52: connectstyle=Direct reliefconductorwidth=10 reliefentries=4 polygonreliefangle="90 Angle" airgapwidth=10
PolygonConnect PolygonConnect_14 [All vs IsNamedPolygon('LAYER_2_VIN_P007')] p53: connectstyle=Direct reliefconductorwidth=10 reliefentries=4 polygonreliefangle="90 Angle" airgapwidth=10
PolygonConnect PolygonConnect_13 [All vs IsNamedPolygon('LAYER_1_(TOP)_VIN_P003')] p54: connectstyle=Direct reliefconductorwidth=10 reliefentries=4 polygonreliefangle="90 Angle" airgapwidth=10
PolygonConnect PolygonConnect_12 [All vs IsNamedPolygon('LAYER_2_PGND_P007')] p55: connectstyle=Direct reliefconductorwidth=10 reliefentries=4 polygonreliefangle="90 Angle" airgapwidth=10
PolygonConnect PolygonConnect_11 [All vs IsNamedPolygon('LAYER_1_(TOP)_AGND_P005')] p56: connectstyle=Direct reliefconductorwidth=10 reliefentries=4 polygonreliefangle="90 Angle" airgapwidth=10
PolygonConnect PolygonConnect_10 [All vs IsNamedPolygon('LAYER_1_(TOP)_VOUT1_P001')] p57: connectstyle=Direct reliefconductorwidth=10 reliefentries=4 polygonreliefangle="90 Angle" airgapwidth=10
PolygonConnect PolygonConnect_9 [All vs IsNamedPolygon('LAYER_1_(TOP)_PGND_P003')] p58: connectstyle=Direct reliefconductorwidth=10 reliefentries=4 polygonreliefangle="90 Angle" airgapwidth=10
PolygonConnect PolygonConnect_8 [All vs IsNamedPolygon('LAYER_1_(TOP)_VIN_P000')] p59: connectstyle=Direct reliefconductorwidth=10 reliefentries=4 polygonreliefangle="90 Angle" airgapwidth=10
PolygonConnect PolygonConnect_7 [All vs IsNamedPolygon('LAYER_1_(TOP)_VOUT2_P001')] p60: connectstyle=Direct reliefconductorwidth=10 reliefentries=4 polygonreliefangle="90 Angle" airgapwidth=10
PolygonConnect PolygonConnect_6 [All vs IsNamedPolygon('LAYER_1_(TOP)_PGND_P002')] p61: connectstyle=Direct reliefconductorwidth=10 reliefentries=4 polygonreliefangle="90 Angle" airgapwidth=10
PolygonConnect PolygonConnect_5 [All vs IsNamedPolygon('LAYER_1_(TOP)_VOUT1_P000')] p62: connectstyle=Direct reliefconductorwidth=10 reliefentries=4 polygonreliefangle="90 Angle" airgapwidth=10
PolygonConnect PolygonConnect_4 [All vs IsNamedPolygon('LAYER_1_(TOP)_VOUT2_P002')] p63: connectstyle=Direct reliefconductorwidth=10 reliefentries=4 polygonreliefangle="90 Angle" airgapwidth=10
PolygonConnect PolygonConnect_3 [All vs IsNamedPolygon('LAYER_1_(TOP)_VOUT1_P000')] p64: connectstyle=Direct reliefconductorwidth=10 reliefentries=4 polygonreliefangle="90 Angle" airgapwidth=10
PolygonConnect PolygonConnect_2 [All vs IsNamedPolygon('LAYER_1_(TOP)_PGND_P001')] p65: thpad.connectstyle=Direct thpad.reliefconductorwidth=10 thpad.reliefentries=4 thpad.polygonreliefangle="90 Angle" thpad.airgapwidth=10 smdpad.connectstyle=Direct smdpad.reliefconductorwidth=10 smdpad.reliefentries=4 smdpad.polygonreliefangle="90 Angle" smdpad.airgapwidth=10 via.connectstyle=Relief via.reliefconductorwidth=10 via.reliefentries=4 via.polygonreliefangle="90 Angle" via.airgapwidth=10
PolygonConnect PolygonConnect_1 [All vs IsNamedPolygon('LAYER_1_(TOP)_PGND_P000')] p66: thpad.connectstyle=Direct thpad.reliefconductorwidth=10 thpad.reliefentries=4 thpad.polygonreliefangle="90 Angle" thpad.airgapwidth=10 smdpad.connectstyle=Direct smdpad.reliefconductorwidth=10 smdpad.reliefentries=4 smdpad.polygonreliefangle="90 Angle" smdpad.airgapwidth=10 via.connectstyle=Relief via.reliefconductorwidth=10 via.reliefentries=4 via.polygonreliefangle="90 Angle" via.airgapwidth=10
PolygonConnect [All] p67: connectstyle=Direct reliefconductorwidth=10 reliefentries=4 polygonreliefangle="90 Angle" airgapwidth=10
RoutingVias ThermalPadVias [IsVia and InAnyComponent] p1: holewidth=7.87 width=19.68 viastyle="Through Hole" minholewidth=6 minwidth=10 maxholewidth=15 maxwidth=23.62
RoutingVias [All] p2: holewidth=16 width=34 viastyle="Through Hole" minholewidth=8 minwidth=16 maxholewidth=40 maxwidth=65
SilkToBoardRegionClearance [Not ((IsComment or IsDesignator) And (Hide <> 'False')) and not InRegion(1000,500,4000,800)] p1:
SilkToSilkClearance SilkToSilkClearance_Pb-FreeLogo [(HasFootprint('Pb-Free_Overlay_Medium') OR HasFootprint('Pb-Free_Overlay_Small')) vs (HasFootprint('Pb-Free_Overlay_Medium') OR HasFootprint('Pb-Free_Overlay_Small'))] p1: silktosilkclearance=0
SilkToSilkClearance [All] p2: silktosilkclearance=2
SilkToSolderMaskClearance SilkToComponentPadClearance [(IsPad or IsFill or IsRegion) and InAnycomponent] p1: minsilkscreentomaskgap=5 clearancetoexposedcopper=TRUE
SilkToSolderMaskClearance "Silk to Solder Mask Opening" [All] p2: minsilkscreentomaskgap=3.94 clearancetoexposedcopper=FALSE
SolderMaskExpansion [All] p1: expansion=1.97 istentingtop=FALSE
UnRoutedNet [All] p1: checkbadconnections=TRUE
Width [All] p1: maxlimit=100 minlimit=4 preferedwidth=10 checkconnectedcopper=TRUE
14 further rules are at their usual default settings.

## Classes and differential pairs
component class Label: LBL1
component class U_DC431_Relay: C116 C117 C118 C119 C120 C121 C122 C123 J8 J9 J10 J11 J12 J13 J14 J15 J16 J17 J18 J19 Q1 Q2 Q3 Q4 Q5 Q6 Q7 Q8 Q9 Q10 Q11 Q12 R179 R180 R181 R182 SH-J3 SH-J4 SH-J5 SH-J6 SH-J7 SH-J8 SH-J9 SH-J10
component class U_DC431_PowerStage: C1 C2 C3 C4 C5 C6 C7 C8 C9 C10 C11 C12 C13 C14 C15 C16 C17 C18 C19 C20 C21 C22 C23 C24 C25 C26 C27 C28 C29 C30 C31 C32 C33 C34 C35 C36 C37 C38 C39 C40 C41 C42 C43 C44 C45 C46 C47 C48 C49 C50 C51 C52 C53 C54 C55 C56 C57 C58 C59 C60 C61 C62 C63 C64 C65 C66 C67 J1 J2 NT1 R1 R2 R3 R4 R5 R6 R7 R8 R9 R10 R11 R12 R13 R14 R15 R16 R17 R18 R19 R20 R21 R22 R23 R24 R25 R26 R27 R28 R29 R30 R31 R32 R33 R34 R35 R36 R37 R38 R39 R40 R41 R42 R43 R44 R45 R46 R47 R48 R49 R50 R51 R52 R53 R54 R55 R56 R57 R58 R59 R60 R61 R62 R63 R64 R65 R66 R67 R68 R69 R70 R71 R72 R73 TP1 TP2 TP3 TP4 TP5 TP6 TP7 TP8 TP9 TP10 TP11 TP12 TP13 TP14 TP15 TP16 TP17 TP18 TP19 TP20 TP21 U1
component class U_DC431_Controller: C109 C110 C111 C112 C113 C114 C115 D3 D4 J5 J6 J7 R116 R117 R118 R119 R120 R121 R122 R123 R124 R125 R126 R127 R128 R129 R130 R131 R132 R133 R134 R135 R136 R137 R138 R139 R140 R141 R142 R143 R144 R145 R146 R147 R148 R149 R150 R151 R152 R153 R154 R155 R156 R157 R158 R159 R160 R161 R162 R163 R164 R165 R166 R167 R168 R169 R170 R171 R172 R173 R174 R175 R176 R177 R178 TP35 TP36 TP37 U11
component class U_DC431_Clamp_Optional: C126 C127 D5 D6 D7 D8 D9 D10 D11 D12 R183 R184 R185 R186 R187 R188 R189 R190 R191 R192 U12 U13
component class U_DC431_BiasPower: C92 C93 C94 C95 C96 C97 C98 C99 C100 C101 C102 C103 C104 C105 C106 C107 C108 D1 D2 J3 J4 L1 L2 R107 R108 R109 R110 R111 R112 R113 R114 R115 SH-J1 SH-J2 TP29 TP30 TP31 TP32 TP33 TP34 U6 U7 U8 U9 U10
component class U_DC431_ADC: C68 C69 C70 C71 C72 C73 C74 C75 C76 C77 C78 C79 C80 C81 C82 C83 C84 C85 C86 C87 C88 C89 C90 C91 R74 R75 R76 R77 R78 R79 R80 R81 R82 R83 R84 R85 R86 R87 R88 R89 R90 R91 R92 R93 R94 R95 R96 R97 R98 R99 R100 R101 R102 R103 R104 R105 R106 TP22 TP23 TP24 TP25 TP26 TP27 TP28 U2 U3 U4 U5
component class Shunt: SH-J1 SH-J2 SH-J3 SH-J4 SH-J5 SH-J6 SH-J7 SH-J8 SH-J9 SH-J10
component class "Mounting Holes": H3 H6 H8 H11
component class DC431_TopLevel: C124 C125 J20 J21 J22 TP38
component class Header: J1 J2 J3 J4 J8 J9 J14 J15
component class Logo: Logo2
component class U_DC431_Hardware: FID1 FID2 FID3 H1 H2 H3 H4 H5 H6 H7 H8 H10 H11 LBL1 Logo1 Logo2 Logo3 Logo4 Logo5 ZZ1 ZZ2 ZZ3 ZZ4
component class FiducialMark: FID1 FID2 FID3
component class AssemblyNote: ZZ1 ZZ2 ZZ3 ZZ4

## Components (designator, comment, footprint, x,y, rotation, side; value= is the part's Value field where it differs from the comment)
C1 "GRM155R71A333KA01D" 0402S 2854.14,3215.96 r180 bottom value=0.033uF
C2 "GRM155R71H122KA01D" 0402S 2752.42,3214 r180 top value=1200pF
C3 "GRM155R71H122KA01D" 0402S 2752.42,2919 r180 top value=1200pF
C4 "GRM155R71A333KA01D" 0402S 2809.57,3143.15 r180 bottom value=0.033uF
C5 "GRM155R71C153KA01D" 0402S 3347.24,4409.25 r0 top value=0.015uF
C6 "C1608X7R1E105K080AB" 0603S 1039.77,4092.17 r180 top value=1uF
C7 "GRM155R71E104KE14D" 0402S 1053.4,4137.68 r180 top value=0.1uF
C8 "EEE-FK1V101P" SM_RADIAL_F 1575.55,3673.3 r180 top value=100uF
C9 "GRM155R71A333KA01D" 0402S 2837.31,2965.67 r180 bottom value=0.033uF
C10 "GRM21BC71E106KE11L" 0805_HV#1 2995.47,3407 r180 top value=10uF
C11 "GRM155R71H122KA01D" 0402S 2754.95,3145.59 r180 top value=1200pF
C12 "GRM155R71H122KA01D" 0402S 2752.42,2853 r180 top value=1200pF
C13 "GRM21BC71E106KE11L" 0805_HV#1 2995.47,3315.43 r180 top value=10uF
C14 "GRM21BC71E106KE11L" 0805_HV#1 2995.47,3315.43 r180 bottom value=10uF
C15 "GRM21BC71E106KE11L" 0805_HV#2 3001.46,2740.44 r180 bottom value=10uF
C16 "GRM21BC71E106KE11L" 0805_HV#1 3001.46,2740.44 r180 top value=10uF
C17 "GRM155R71A333KA01D" 0402S 2846.66,2859.69 r180 bottom value=0.033uF
C18 "GRM155R61E225ME15D" 0402S 3005.42,3039 r180 bottom value=2.2uF
C19 "GRM21BC71E106KE11L" 0805_HV#1 2995.47,3407 r180 bottom value=10uF
C20 "GRM21BC71E106KE11L" 0805_HV#1 3001.46,2662.18 r180 bottom value=10uF
C21 "GRM21BC71E106KE11L" 0805_HV#1 3001.46,2662.18 r180 top value=10uF
C22 "GRM155R61E225ME15D" 0402S 3005.42,3084 r180 bottom value=2.2uF
C23 "GRM155R61E225ME15D" 0402S 3005.42,3000 r180 bottom value=2.2uF
C24 "GRM155R61E225ME15D" 0402S 3005.42,2960.5 r180 bottom value=2.2uF
C25 "GRM155R71C153KA01D" 0402S 3349.83,3972.42 r0 top value=0.015uF
C26 "GRM155R71E104KE14D" 0402S 3234.42,3262.72 r270 top value=0.1uF
C27 "GRM155R71E104KE14D" 0402S 3234.42,3114.15 r90 top value=0.1uF
C28 "GRM155R71E104KE14D" 0402S 3234.42,2948.8 r270 top value=0.1uF
C29 "GRM155R71E104KE14D" 0402S 3234.21,2751.59 r90 top value=0.1uF
C30 "GRM155R71C153KA01D" 0402S 3832.52,4409.39 r0 top value=0.015uF
C31 "C2012X7S1A226M125AC" 0805_HV#1 3291.67,3275.43 r270 bottom value=22uF
C32 "C2012X7S1A226M125AC" 0805_HV#1 3291.67,3115.58 r90 top value=22uF
C33 "C2012X7S1A226M125AC" 0805_HV#1 3291.67,2939.34 r270 bottom value=22uF
C34 "C2012X7S1A226M125AC" 0805_HV#1 3291.67,2748.89 r90 bottom value=22uF
C35 "C2012X7S1A226M125AC" 0805_HV#1 3291.67,3275.43 r270 top value=22uF
C36 "C2012X7S1A226M125AC" 0805_HV#1 3291.67,3115.58 r90 bottom value=22uF
C37 "C2012X7S1A226M125AC" 0805_HV#1 3291.67,2939.34 r270 top value=22uF
C38 "C2012X7S1A226M125AC" 0805_HV#1 3291.67,2748.9 r90 top value=22uF
C39 "LMK325B7476MM-PR" 1210_270 3530.69,3294.03 r270 top value=47uF
C40 "LMK325B7476MM-PR" 1210_270 3530.69,3116.07 r90 top value=47uF
C41 "LMK325B7476MM-PR" 1210_270 3391.78,2932.32 r270 top value=47uF
C42 "LMK325B7476MM-PR" 1210_270 3391.78,2740.94 r90 top value=47uF
C43 "LMK325B7476MM-PR" 1210_270 3391.78,3294.03 r270 top value=47uF
C44 "LMK325B7476MM-PR" 1210_270 3391.78,3116.07 r90 top value=47uF
C45 "LMK325B7476MM-PR" 1210_270 3530.69,2932.32 r270 top value=47uF
C46 "LMK325B7476MM-PR" 1210_270 3530.69,2740.94 r90 top value=47uF
C47 "LMK325B7476MM-PR" 1210_270 3391.78,3294.03 r270 bottom value=47uF
C48 "LMK325B7476MM-PR" 1210_270 3391.78,3116.07 r90 bottom value=47uF
C49 "LMK325B7476MM-PR" 1210_270 3391.78,2932.32 r270 bottom value=47uF
C50 "LMK325B7476MM-PR" 1210_270 3391.78,2740.94 r90 bottom value=47uF
C51 "LMK325B7476MM-PR" 1210_270 3663.52,3294.03 r270 top value=47uF
C52 "LMK325B7476MM-PR" 1210_270 3663.52,3116.07 r90 top value=47uF
C53 "LMK325B7476MM-PR" 1210_270 3663.52,2932.32 r270 top value=47uF
C54 "LMK325B7476MM-PR" 1210_270 3663.52,2740.94 r90 top value=47uF
C55 "GRM155R71C153KA01D" 0402S 3831.43,3972.42 r0 top value=0.015uF
C56 "LMK325B7476MM-PR" 1210_270 3530.69,3294.03 r270 bottom value=47uF
C57 "LMK325B7476MM-PR" 1210_270 3530.69,3116.07 r90 bottom value=47uF
C58 "LMK325B7476MM-PR" 1210_270 3530.69,2932.32 r270 bottom value=47uF
C59 "LMK325B7476MM-PR" 1210_270 3530.69,2740.94 r90 bottom value=47uF
C60 "LMK325B7476MM-PR" 1210_270 3663.52,3294.03 r270 bottom value=47uF
C61 "LMK325B7476MM-PR" 1210_270 3663.52,3116.07 r90 bottom value=47uF
C62 "LMK325B7476MM-PR" 1210_270 3663.52,2932.32 r270 bottom value=47uF
C63 "LMK325B7476MM-PR" 1210_270 3663.52,2740.94 r90 bottom value=47uF
C64 "GRM155R61C104KA88D" 0402S 3921.52,3543.88 r180 bottom value=0.1uF
C65 "GRM155R61C104KA88D" 0402S 3926.22,3287.93 r180 bottom value=0.1uF
C66 "GRM155R61C104KA88D" 0402S 3932.81,2764.12 r180 bottom value=0.1uF
C67 "GRM155R61C104KA88D" 0402S 3931.23,2494.11 r180 bottom value=0.1uF
C68 "CGA3E1X7R1E105K080AC" 0603S 2918.98,1253.91 r270 top value=1uF
C69 "CGA3E1X7R1E105K080AC" 0603S 3194.25,1114.64 r270 top value=1uF
C70 "GRM188R61E106MA73D" 0603S 2833.7,2170.06 r90 top value=10uF
C71 "CGA3E1X7R1E105K080AC" 0603S 3016.7,1997.06 r0 top value=1uF
C72 "GRM188R61E106MA73D" 0603S 3256.85,1114.27 r270 top value=10uF
C73 "CGA3E1X7R1E105K080AC" 0603S 3452.7,2248.06 r90 top value=1uF
C74 "CGA3E1X7R1E105K080AC" 0603S 3299.45,1993.92 r180 top value=1uF
C75 "GRM155R61C104KA88D" 0402S 3413.63,2241.34 r90 top value=0.1uF
C76 "GRM155R61C104KA88D" 0402S 3287,2033.15 r180 top value=0.1uF
C77 "GRM155R61C104KA88D" 0402S 3028.63,2037.84 r0 top value=0.1uF
C78 "GRM155R61C104KA88D" 0402S 2876.37,2220.07 r270 top value=0.1uF
C79 "GRM155R61C104KA88D" 0402S 2908.8,2220.07 r270 top value=0.1uF
C80 "GRM155R61C104KA88D" 0402S 3389.05,2118.73 r180 top value=0.1uF
C81 "GRM155R61C104KA88D" 0402S 2918.7,2116.06 r0 top value=0.1uF
C82 "CGA3E1X7R1E105K080AC" 0603S 2888.12,2077.84 r0 top value=1uF
C83 "GRM188R61E106MA73D" 0603S 3444.45,2077.05 r0 top value=10uF
C84 "GRM155R61C104KA88D" 0402S 2826.7,2309.06 r90 top value=0.1uF
C85 "GRM035R60J475ME15D" 0201 3387.09,2165.32 r90 top value=4.7uF
C86 "GRM188Z71A106MA73D" 0603S 3504.7,2168.06 r0 top value=10uF
C87 "GRM035R60J475ME15D" 0201 2952.7,2178.06 r90 top value=4.7uF
C88 "CGA3E1X7R1E105K080AC" 0603S 2387.09,3278.87 r180 top value=1uF
C89 "GRM155R61C104KA88D" 0402S 2379.47,3239.75 r0 top value=0.1uF
C90 "GRM155R61C104KA88D" 0402S 2430.29,3048.84 r0 top value=0.1uF
C91 "CGA3E1X7R1E105K080AC" 0603S 2441.15,3009.99 r180 top value=1uF
C92 "CGA3E1X7R1E105K080AC" 0603S 661.55,3442.15 r90 top value=1uF
C93 "GRM155R61C104KA88D" 0402S 533.77,3457.2 r90 top value=0.1uF
C94 "F381A225MMA" 0603S 303.39,3432.1 r90 top value=2.2uF
C95 "CGA3E1X7R1E105K080AC" 0603S 819.09,3411.28 r90 top value=1uF
C96 "CGA3E1X7R1E105K080AC" 0603S 900.61,3305.83 r180 top value=1uF
C97 "GMK325BJ226MM-P" 1210 318.36,4070.58 r0 top value=22uF
C98 "CGA3E1X7R1E105K080AC" 0603S 359.28,3151.73 r270 top value=1uF
C99 "GRM188R72A104KA35D" 0603S 184.06,4070.58 r90 top value=0.1uF
C100 "GRM155R61C104KA88D" 0402S 350.42,3081.23 r0 top value=0.1uF
C101 "CGA3E1X7R1E105K080AC" 0603S 1039.09,3378.8 r90 top value=1uF
C102 "GRM188R72A104KA35D" 0603S 156.79,3891.87 r270 top value=0.1uF
C103 "CGA3E1X7R1E105K080AC" 0603S 682.01,3112.73 r270 top value=1uF
C104 "GMK325BJ226MM-P" 1210 617,3782.33 r270 top value=22uF
C105 "GMK325BJ226MM-P" 1210 762.9,3781.62 r270 top value=22uF
C106 "CGA3E1X7R1E105K080AC" 0603S 441.61,2754.8 r180 top value=1uF
C107 "GRM155R61C104KA88D" 0402S 454.09,2668.25 r0 top value=0.1uF
C108 "CGA3E1X7R1E105K080AC" 0603S 771.06,2724.82 r270 top value=1uF
C109 "GRM155R61C104KA88D" 0402S 3761.88,628.03 r90 top value=0.1uF
C110 "GCM155R71C224KE02D" 0402S 3770.48,172.6 r180 top value=0.22uF
C111 "GRM1555C1H151JA01D" 0402S 3890.11,172.6 r180 top value=150pF
C112 "GRM155R61C104KA88D" 0402S 3584.24,172.6 r180 top value=0.1uF
C113 "GRM155R61C104KA88D" 0402S 2837.69,152.2 r90 top value=0.1uF
C114 "GRM155R61C104KA88D" 0402S 2618.02,152.2 r90 top value=0.1uF
C115 "GRM155R61C104KA88D" 0402S 2398.73,152.2 r90 top value=0.1uF
C116 "CL10B105KO8VPNC" 0603S 4541.53,4243.15 r0 top value=1uF
C117 "CL10B105KO8VPNC" 0603S 5271.33,3800.83 r90 top value=1uF
C118 "GRM188R71C223KA01D" 0603S 4541.26,4288.1 r0 top value=0.022uF
C119 "GRM188R71C223KA01D" 0603S 5320,3801.11 r90 top value=0.022uF
C120 "CL10B105KO8VPNC" 0603S 5349.8,2711.32 r270 top value=1uF
C121 "CL10B105KO8VPNC" 0603S 5267.57,1643.48 r90 top value=1uF
C122 "GRM188R71C223KA01D" 0603S 5303.36,2711.25 r270 top value=0.022uF
C123 "GRM188R71C223KA01D" 0603S 5314.8,1643.48 r90 top value=0.022uF
C124 "C1608X7R1E105K080AB" 0603S 1810.79,4026.56 r0 top value=1uF
C125 "GRM155R71E104KE14D" 0402S 1797.01,4072.49 r0 top value=0.1uF
C126 "GRM155R61C104KA88D" 0402S 2244.22,2779.27 r0 top value=0.1uF
C127 "GRM155R61C104KA88D" 0402S 2282.79,2415.24 r0 top value=0.1uF
D1 "150060VS75000" WL-SMCW_GREEN 1001.57,3116.68 r270 top value=Green
D2 "150060VS75000" WL-SMCW_GREEN 1058.6,2719.37 r270 top value=Green
D3 "150060VS75000" WL-SMCW_GREEN 1158.96,652.49 r0 top value=Green
D4 "150060VS75000" WL-SMCW_GREEN 872.19,2396.12 r270 top value=Green
D5 "1N4148WL2-TP" FP-1N4148WL2-TP_DFN1006-MFG 2307.33,2887.97 r180 top
D6 "1N4148WL2-TP" FP-1N4148WL2-TP_DFN1006-MFG 2306.28,2676.48 r180 top
D7 "1N4148WL2-TP" FP-1N4148WL2-TP_DFN1006-MFG 2428.6,2675.99 r0 top
D8 "1N4148WL2-TP" FP-1N4148WL2-TP_DFN1006-MFG 2422.42,2887.97 r0 top
D9 "1N4148WL2-TP" FP-1N4148WL2-TP_DFN1006-MFG 2369.71,2520.25 r0 top
D10 "1N4148WL2-TP" FP-1N4148WL2-TP_DFN1006-MFG 2356.74,2304.57 r0 top
D11 "1N4148WL2-TP" FP-1N4148WL2-TP_DFN1006-MFG 2430.2,2304.57 r180 top
D12 "1N4148WL2-TP" FP-1N4148WL2-TP_DFN1006-MFG 2436.83,2520 r180 top
FID1 "Fiducial" Fiducial10-20 420.53,593.2 r0 top
FID2 "Fiducial" Fiducial10-20 5558,596.7 r0 top
FID3 "Fiducial" Fiducial10-20 420.53,4730 r0 top
H1 "1902C" Keystone_1902C 205.3,4589.97 r180 bottom locked
H2 "9774050360R" Wurth_WA-SMSI 545.5,1037.46 r180 top
H3 "NY PMS 440 0025 PH" "NY PMS 440 0025 PH" 205.3,4589.97 r0 top
H4 "9774050360R" Wurth_WA-SMSI 545.5,2317.46 r180 top
H5 "1902C" Keystone_1902C 5500.36,4589.97 r180 bottom
H6 "NY PMS 440 0025 PH" "NY PMS 440 0025 PH" 5500.36,4589.97 r0 top
H7 "1902C" Keystone_1902C 205.3,200 r180 bottom
H8 "NY PMS 440 0025 PH" "NY PMS 440 0025 PH" 205.3,200 r0 top
H10 "1902C" Keystone_1902C 5500.36,200 r180 bottom
H11 "NY PMS 440 0025 PH" "NY PMS 440 0025 PH" 5500.36,200 r0 top
J1 "TSW-105-07-G-D" TSW-105-07-G-D 5169.67,390.24 r270 top
J2 "TSW-105-07-G-D" TSW-105-07-G-D 4821.22,390.24 r270 top
J3 "HTSW-103-07-G-S" Samtec_HTSW-103-07-G-S 242.74,4304.95 r0 top
J4 "HTSW-102-07-G-S" Samtec_HTSW-102-07-G-S 918.65,3773.18 r270 top
J5 "HSEC8-160-01-L-DV-A-BL" controlCARD-120HSEC 3335.82,380.87 r180 top
J6 "HSEC8-130-01-L-DV-A" controlCARD-180HSEC-60pinAddon 987.82,379.13 r180 top
J7 "PHI" Samtec_QTH-030-01-x-D-A 375.5,1677.46 r90 top
J8 "TSW-102-07-G-D" TSW-102-07-G-D 4527.79,4093.27 r0 top
J9 "TSW-102-07-G-D" TSW-102-07-G-D 5080.07,3801.11 r270 top
J10 "CMP-0055165-2" Keystone_575-4 5440.36,4060.59 r0 top
J11 "CMP-0055165-2" Keystone_575-4 4359.11,4496.72 r90 top
J12 "CMP-0055165-2" Keystone_575-4 4880.67,4496.72 r90 top
J13 "CMP-0055165-2" Keystone_575-4 5440.36,3518.16 r0 top
J14 "TSW-102-07-G-D" TSW-102-07-G-D 5055.59,2743.71 r270 top
J15 "TSW-102-07-G-D" TSW-102-07-G-D 5042.98,1638 r270 top
J16 "CMP-0055165-2" Keystone_575-4 5440.36,2433.3 r0 top
J17 "CMP-0055165-2" Keystone_575-4 5440.36,1890.87 r0 top
J18 "CMP-0055165-2" Keystone_575-4 5440.36,2975.73 r0 top
J19 "CMP-0055165-2" Keystone_575-4 5440.36,1348.44 r0 top
J20 "PJ-102A" CONN_PJ-102A 1708.9,4270 r90 top
J21 "CMP-0055165-2" Keystone_575-4 1180.94,4414.96 r90 top
J22 "CMP-0055165-2" Keystone_575-4 644.6,4414.96 r90 top
L1 "BLM41PG102SN1L" 1806_HighSpeed 832.39,3595.53 r180 top value="1000 ohm"
L2 "LPS5015-183MLB" LPS5015 412.29,3705.76 r0 top value=18uH
LBL1 "THT-14-423-10" Label_650x200 2615.65,762 r0 top
Logo1 "CAUTION HOT SURFACE" IEC_HotSurface_Medium 1775.36,3229.84 r0 top
Logo2 "Texas Instruments" TI_Stacked_Overlay_Small 1760,778.8 r0 top
Logo3 "CE Mark" CE_Mark_5mm 648.82,680.05 r0 top
Logo4 "FCC disclaimer" FCC_disclaimer 1333.83,100 r0 top
Logo5 "WEEE logo" WEEE_Minimum 180,674.14 r0 top
NT1 "Net-Tie" Net-Tie_10milWide_30milLong 2925.65,3250.02 r180 bottom net-tie
Q1 "2N7002Q-7-F" SOT-23 4720.25,3986.2 r180 top value=60V
Q2 "2N7002Q-7-F" SOT-23 5028.58,3373.25 r90 top value=60V
Q3 "APV2111VY" FP-APV2111VY_SSOP4-MFG 4882.85,3412.48 r90 top
Q4 "APV2111VY" FP-APV2111VY_SSOP4-MFG 4590,3833.24 r180 top
Q5 "CSD87503Q3E" DTD0008A-MFG 4775.59,3622.67 r90 top
Q6 "CSD87503Q3E" DTD0008A-MFG 4316.26,3773.4 r180 top
Q7 "2N7002Q-7-F" SOT-23 4949.63,2509.51 r90 top value=60V
Q8 "2N7002Q-7-F" SOT-23 5000.97,1125.59 r90 top value=60V
Q9 "APV2111VY" FP-APV2111VY_SSOP4-MFG 4807.36,2595.63 r90 top
Q10 "APV2111VY" FP-APV2111VY_SSOP4-MFG 4865.86,1227.7 r90 top
Q11 "CSD87503Q3E" DTD0008A-MFG 4805.25,2829.17 r90 top
Q12 "CSD87503Q3E" DTD0008A-MFG 4862.37,1446.02 r90 top
R1 "CRCW040229K4FKED" 0402S 2681.65,3040.57 r180 top value=29.4k
R2 "CRCW040240K2FKED" 0402S 2790.24,3065.69 r0 bottom value=40.2k
R3 "CRCW040210K5FKED" 0402S 2818.42,3214 r0 top value=10.5k
R4 "CRCW040210K5FKED" 0402S 2818.42,2919 r0 top value=10.5k
R5 "RT0603BRD0710KL" 0603S 3274.15,4381.25 r270 top value=10.0k
R6 "RT0603BRD0710KL" 0603S 3421.1,4381.25 r270 top value=10.0k
R7 "CRCW040229K4FKED" 0402S 2681.65,3002 r180 top value=29.4k
R8 "CRCW040240K2FKED" 0402S 2862.26,2817.98 r0 bottom value=40.2k
R9 "CRCW040210K5FKED" 0402S 2818.42,3146 r0 top value=10.5k
R10 "CRCW040210K5FKED" 0402S 2818.42,2853 r0 top value=10.5k
R11 "RT0603BRD0710KL" 0603S 3274.15,3944.42 r270 top value=10.0k
R12 "RT0603BRD0710KL" 0603S 3421.1,3944.42 r270 top value=10.0k
R13 "CRCW040210K0FKED" 0402S 2644.92,3319.8 r90 bottom value=10.0k
R14 "RT0603BRD0710KL" 0603S 3761.04,4381.39 r270 top value=10.0k
R15 "RT0603BRD0710KL" 0603S 3899.6,4381.39 r270 top value=10.0k
R16 "CRCW040210K0FKED" 0402S 2654.09,3448.85 r180 top value=10.0k
R17 "CRCW040210K0FKED" 0402S 2585.04,3448.85 r0 top value=10.0k
R18 "RT0603BRD0710KL" 0603S 3761.04,3944.42 r270 top value=10.0k
R19 "RT0603BRD0710KL" 0603S 3899.6,3944.42 r270 top value=10.0k
R20 "CRCW040210K0FKED" 0402S 2606.16,2736.42 r0 top value=10.0k
R21 "CRCW040210K0FKED" 0402S 2675.74,2736.42 r180 top value=10.0k
R22 "CRCW04020000Z0ED" 0402S 3745.42,2941.84 r270 bottom value=0
R23 "CRCW04020000Z0ED" 0402S 3801.85,2537.18 r270 bottom value=0
R24 "CRCW04020000Z0ED" 0402S 3801.85,3508.27 r90 bottom value=0
R25 "CRCW04020000Z0ED" 0402S 3745.42,3099.38 r90 bottom value=0
R26 "CRCW040210K0FKED" 0402S 2776.23,3316.25 r180 top value=10.0k
R27 "CRCW04021K87FKED" 0402S 2776.61,3283.12 r0 top value=1.87k
R28 "CRCW04024K99FKED" 0402S 2776.5,3250.71 r180 top value=4.99k
R29 "CRCW040210K0FKED" 0402S 2684.37,3185.81 r180 top value=10.0k
R30 "CRCW04021K87FKED" 0402S 2684.07,3119.58 r0 top value=1.87k
R31 "CRCW06031R00FKEA" 0603S 3892.6,3483.49 r270 bottom value=1.00
R32 "CRCW040210K0FKED" 0402S 2815.92,2730.14 r270 top value=10.0k
R33 "CRCW04021K87FKED" 0402S 2783.14,2730.14 r90 top value=1.87k
R34 "CRCW04024K99FKED" 0402S 2684.31,3151.74 r180 top value=4.99k
R35 "TLRP3A20CR004FTE" FP-TLRP3A20CR080FTE_2512-MFG 3929.73,3362.51 r0 top value=4m
R36 "CRCW04024K99FKED" 0402S 2750.89,2730.14 r270 top value=4.99k
R37 "CRCW06031R00FKEA" 0603S 3901.58,3224.71 r270 bottom value=1.00
R38 "CRCW04021K87FKED" 0402S 2648.97,2935.46 r0 top value=1.87k
R39 "CRCW040210K0FKED" 0402S 2648.47,2867.73 r180 top value=10.0k
R40 "TLRP3A20CR004FTE" FP-TLRP3A20CR080FTE_2512-MFG 3930.03,3106.74 r0 top value=4m
R41 "CRCW06031R00FKEA" 0603S 3948.02,3483.49 r270 bottom value=1.00
R42 "CRCW04020000Z0ED" 0402S 3717.27,1832.72 r180 bottom value=0
R43 "CRCW04020000Z0ED" 0402S 3717.27,1832.72 r180 top value=0
R44 "CRCW04020000Z0ED" 0402S 3717.27,1731.68 r180 bottom value=0
R45 "CRCW04020000Z0ED" 0402S 3717.27,1731.68 r180 top value=0
R46 "CRCW04020000Z0ED" 0402S 3717.27,1631.68 r180 bottom value=0
R47 "CRCW04020000Z0ED" 0402S 3717.27,1631.68 r180 top value=0
R48 "CRCW04020000Z0ED" 0402S 3717.27,1531.68 r180 bottom value=0
R49 "CRCW04020000Z0ED" 0402S 3717.27,1531.68 r180 top value=0
R50 "CRCW04020000Z0ED" 0402S 3717.27,1412.22 r180 top value=0
R51 "CRCW04020000Z0ED" 0402S 3717.27,1311.18 r180 top value=0
R52 "CRCW04024K99FKED" 0402S 2648.18,2902.01 r180 top value=4.99k
R53 "CRCW06031R00FKEA" 0603S 3953.45,3225.16 r270 bottom value=1.00
R54 "CRCW06031R00FKEA" 0603S 3906.27,2824.72 r90 bottom value=1.00
R55 "TLRP3A20CR004FTE" FP-TLRP3A20CR080FTE_2512-MFG 3929.73,2944.15 r0 top value=4m
R56 "CRCW06031R00FKEA" 0603S 3908.18,2555.92 r90 bottom value=1.00
R57 "CRCW06031R00FKEA" 0603S 3956.27,2824.72 r90 bottom value=1.00
R58 "TLRP3A20CR004FTE" FP-TLRP3A20CR080FTE_2512-MFG 3929.73,2679.49 r0 top value=4m
R59 "CRCW06031R00FKEA" 0603S 3955.74,2555.92 r90 bottom value=1.00
R60 "CRCW04020000Z0ED" 0402S 3946.8,1831.59 r180 bottom value=0
R61 "CRCW04020000Z0ED" 0402S 3946.8,1831.59 r180 top value=0
R62 "CRCW04020000Z0ED" 0402S 3946.8,1730.55 r180 bottom value=0
R63 "CRCW04020000Z0ED" 0402S 3946.8,1730.55 r180 top value=0
R64 "CRCW04020000Z0ED" 0402S 3946.8,1630.55 r180 bottom value=0
R65 "CRCW04020000Z0ED" 0402S 3946.8,1630.55 r180 top value=0
R66 "CRCW04020000Z0ED" 0402S 3717.27,1211.18 r180 bottom value=0
R67 "CRCW04020000Z0ED" 0402S 3717.27,1211.18 r180 top value=0
R68 "CRCW04020000Z0ED" 0402S 3946.8,1530.55 r180 bottom value=0
R69 "CRCW04020000Z0ED" 0402S 3946.8,1530.55 r180 top value=0
R70 "CRCW04020000Z0ED" 0402S 3850.74,3239.07 r270 bottom value=0
R71 "CRCW04020000Z0ED" 0402S 3742.43,3203.99 r90 bottom value=0
R72 "CRCW04020000Z0ED" 0402S 3770.28,2835.29 r270 bottom value=0
R73 "CRCW04020000Z0ED" 0402S 3848.33,2804.12 r90 bottom value=0
R74 "CRCW04020000Z0ED" 0402S 3315.6,1238.46 r0 top value=0
R75 "ERJ-2BQFR22X" 0402S 3256.6,1214.14 r90 top value=0.22
R76 "CRCW04020000Z0ED" 0402S 3111.49,1773.45 r270 top value=0
R77 "CRCW04020000Z0ED" 0402S 3062.61,1773.45 r270 top value=0
R78 "CRCW04020000Z0ED" 0402S 3160.37,1773.45 r270 top value=0
R79 "CRCW04020000Z0ED" 0402S 3013.73,1773.45 r270 top value=0
R80 "CRCW04020000Z0ED" 0402S 3258.13,1773.45 r270 top value=0
R81 "CRCW04020000Z0ED" 0402S 3209.25,1773.45 r270 top value=0
R82 "CRCW04020000Z0ED" 0402S 3307.01,1773.45 r270 top value=0
R83 "CRCW04020000Z0ED" 0402S 3355.89,1773.45 r270 top value=0
R84 "CRCW04020000Z0ED" 0402S 2964.85,1773.45 r270 top value=0
R85 "CRCW04020000Z0ED" 0402S 2875.12,2284.76 r180 top value=0
R86 "RT0603BRD0710KL" 0603S 2895.34,1831.43 r180 top value=10.0k
R87 "RT0603BRD0710KL" 0603S 2833.78,1879.61 r180 top value=10.0k
R88 "RT0603BRD0710KL" 0603S 2982.43,1616.77 r180 top value=10.0k
R89 "CRCW04020000Z0ED" 0402S 2792.79,2308.31 r270 top value=0
R90 "CRCW04020000Z0ED" 0402S 2505.22,3131.89 r180 top value=0
R91 "CRCW04020000Z0ED" 0402S 2505.69,3165.64 r180 top value=0
R92 "CRCW04020000Z0ED" 0402S 2505.55,3199.27 r180 top value=0
R93 "CRCW04020000Z0ED" 0402S 2445.05,3239.36 r180 top value=0
R94 "CRCW04020000Z0ED" 0402S 2313.69,3240.42 r0 top value=0
R95 "CRCW04020000Z0ED" 0402S 2260.79,3194.87 r0 top value=0
R96 "CRCW04020000Z0ED" 0402S 2260.9,3161.7 r0 top value=0
R97 "CRCW04020000Z0ED" 0402S 2260.64,3129.43 r0 top value=0
R98 "CRCW04020000Z0ED" 0402S 4150.54,1291.18 r0 top value=0
R99 "RT0603BRD075K05L" 0603S 4229.69,1244.17 r0 top value=5.05k
R100 "RT0603BRD0710KL" 0603S 4230.08,1179.37 r0 top value=10.0k
R101 "RT0603BRD0710KL" 0603S 4331.54,1243.16 r0 top value=10.0k
R102 "CRCW04020000Z0ED" 0402S 4240.45,1104 r180 top value=0
R103 "CRCW04020000Z0ED" 0402S 4239.53,1062.81 r180 top value=0
R104 "CRCW04020000Z0ED" 0402S 4239.53,1022.75 r180 top value=0
R105 "CRCW04020000Z0ED" 0402S 4477.78,1143.4 r0 top value=0
R106 "CRCW04020000Z0ED" 0402S 4477.78,1183.62 r0 top value=0
R107 "CRCW06031K00JNEA" 0603S 585.64,3442.15 r90 top value=1.0k
R108 "CRCW06031K00JNEA" 0603S 426.32,3105.86 r270 top value=1.0k
R109 "CRCW0402124KFKED" 0402S 434.31,3857.85 r0 top value=124k
R110 "CRCW040222K1FKED" 0402S 385.09,3919.34 r0 top value=22.1k
R111 "CRCW06031K00JNEA" 0603S 929.38,3121.73 r90 top value=1.0k
R112 "CRCW12060000Z0EAC" FP-CRCW12060000Z0EAC_1206-MFG 228.34,3665.86 r90 top value=0
R113 "CRCW12060000Z0EAC" FP-CRCW12060000Z0EAC_1206-MFG 648.25,3603.52 r270 top value=0
R114 "CRCW06031K00JNEA" 0603S 522.97,2719.37 r270 top value=1.0k
R115 "CRCW06031K00JNEA" 0603S 981.48,2728.23 r90 top value=1.0k
R116 "CRCW040222R0JNED" 0402S 1537.16,1181.96 r180 bottom value=22
R117 "CRCW040222R0JNED" 0402S 1537.16,1220.76 r180 bottom value=22
R118 "CRCW040222R0JNED" 0402S 1537.16,1259.57 r180 bottom value=22
R119 "CRCW040222R0JNED" 0402S 1537.16,1298.37 r180 bottom value=22
R120 "CRCW040222R0JNED" 0402S 1537.16,1706.1 r180 bottom value=22
R121 "CRCW040222R0JNED" 0402S 1537.16,2017.05 r180 bottom value=22
R122 "CRCW040222R0JNED" 0402S 1537.16,1847.46 r180 bottom value=22
R123 "CRCW040222R0JNED" 0402S 1537.16,1779.39 r180 bottom value=22
R124 "CRCW040222R0JNED" 0402S 1537.16,2059.2 r180 bottom value=22
R125 "CRCW040222R0JNED" 0402S 1537.16,1882.16 r180 bottom value=22
R126 "CRCW040222R0JNED" 0402S 1537.16,1811.96 r180 bottom value=22
R127 "CRCW040222R0JNED" 0402S 1537.16,1917.65 r180 bottom value=22
R128 "CRCW040222R0JNED" 0402S 1537.16,1967.32 r180 bottom value=22
R129 "CRCW040222R0JNED" 0402S 1537.16,1422.38 r180 bottom value=22
R130 "CRCW040222R0JNED" 0402S 1537.16,1471.54 r180 bottom value=22
R131 "CRCW040222R0JNED" 0402S 1537.16,2174.6 r180 bottom value=22
R132 "CRCW040222R0JNED" 0402S 1537.16,1136.86 r180 bottom value=22
R133 "CRCW040222R0JNED" 0402S 1537.16,2215.27 r180 bottom value=22
R134 "CRCW040222R0JNED" 0402S 1537.16,2264.65 r180 bottom value=22
R135 "CRCW040222R0JNED" 0402S 1537.16,2314.72 r180 bottom value=22
R136 "CRCW040222R0JNED" 0402S 1537.16,2363.65 r180 bottom value=22
R137 "ERA-2AEB102X" 0402S 3567.26,648.67 r0 top value=1.00k
R138 "CRCW040222R0JNED" 0402S 1537.16,1619.82 r0 bottom value=22
R139 "CRCW040222R0JNED" 0402S 1537.16,1743.65 r0 bottom value=22
R140 "CRCW040222R0JNED" 0402S 1537.16,1337.37 r0 bottom value=22
R141 "CRCW040222R0JNED" 0402S 1537.16,1375.98 r0 bottom value=22
R142 "CRCW040222R0JNED" 0402S 1537.16,1670.16 r0 bottom value=22
R143 "CRCW040222R0JNED" 0402S 1537.16,2116.65 r0 bottom value=22
R144 "CRCW040222R0JNED" 0402S 1537.16,1522.73 r0 bottom value=22
R145 "CRCW040222R0JNED" 0402S 1537.16,1571.57 r0 bottom value=22
R146 "PCF0402-12-2K74BT1" 0402S 3850.93,83.63 r180 top value=2.74k
R147 "ERA-2AEB102X" 0402S 3917.67,83.63 r0 top value=1.00k
R148 "ERA-2AEB102X" 0402S 1215.69,601.61 r0 top value=1.00k
R149 "CRCW040222R0JNED" 0402S 1537.09,1422.38 r180 top value=22
R150 "CRCW040222R0JNED" 0402S 1537.09,1471.93 r180 top value=22
R151 "CRCW040222R0JNED" 0402S 1537.09,1521.49 r180 top value=22
R152 "CRCW040222R0JNED" 0402S 1537.09,1571.04 r180 top value=22
R153 "CRCW040222R0JNED" 0402S 1537.09,1620.6 r180 top value=22
R154 "CRCW040222R0JNED" 0402S 1537.09,1670.16 r180 top value=22
R155 "CRCW040222R0JNED" 0402S 1537.09,1706.1 r180 top value=22
R156 "CRCW040222R0JNED" 0402S 1537.09,1744.16 r180 top value=22
R157 "CRCW040222R0JNED" 0402S 1537.09,1811.96 r180 top value=22
R158 "CRCW040222R0JNED" 0402S 1537.09,1881.95 r180 top value=22
R159 "CRCW040222R0JNED" 0402S 1537.09,1917.93 r180 top value=22
R160 "CRCW040222R0JNED" 0402S 1537.09,1967.49 r180 top value=22
R161 "CRCW040222R0JNED" 0402S 1537.09,2017.05 r180 top value=22
R162 "CRCW040222R0JNED" 0402S 1537.09,2060.93 r180 top value=22
R163 "CRCW040222R0JNED" 0402S 1537.09,2116.16 r180 top value=22
R164 "CRCW040222R0JNED" 0402S 1537.09,2174.6 r180 top value=22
